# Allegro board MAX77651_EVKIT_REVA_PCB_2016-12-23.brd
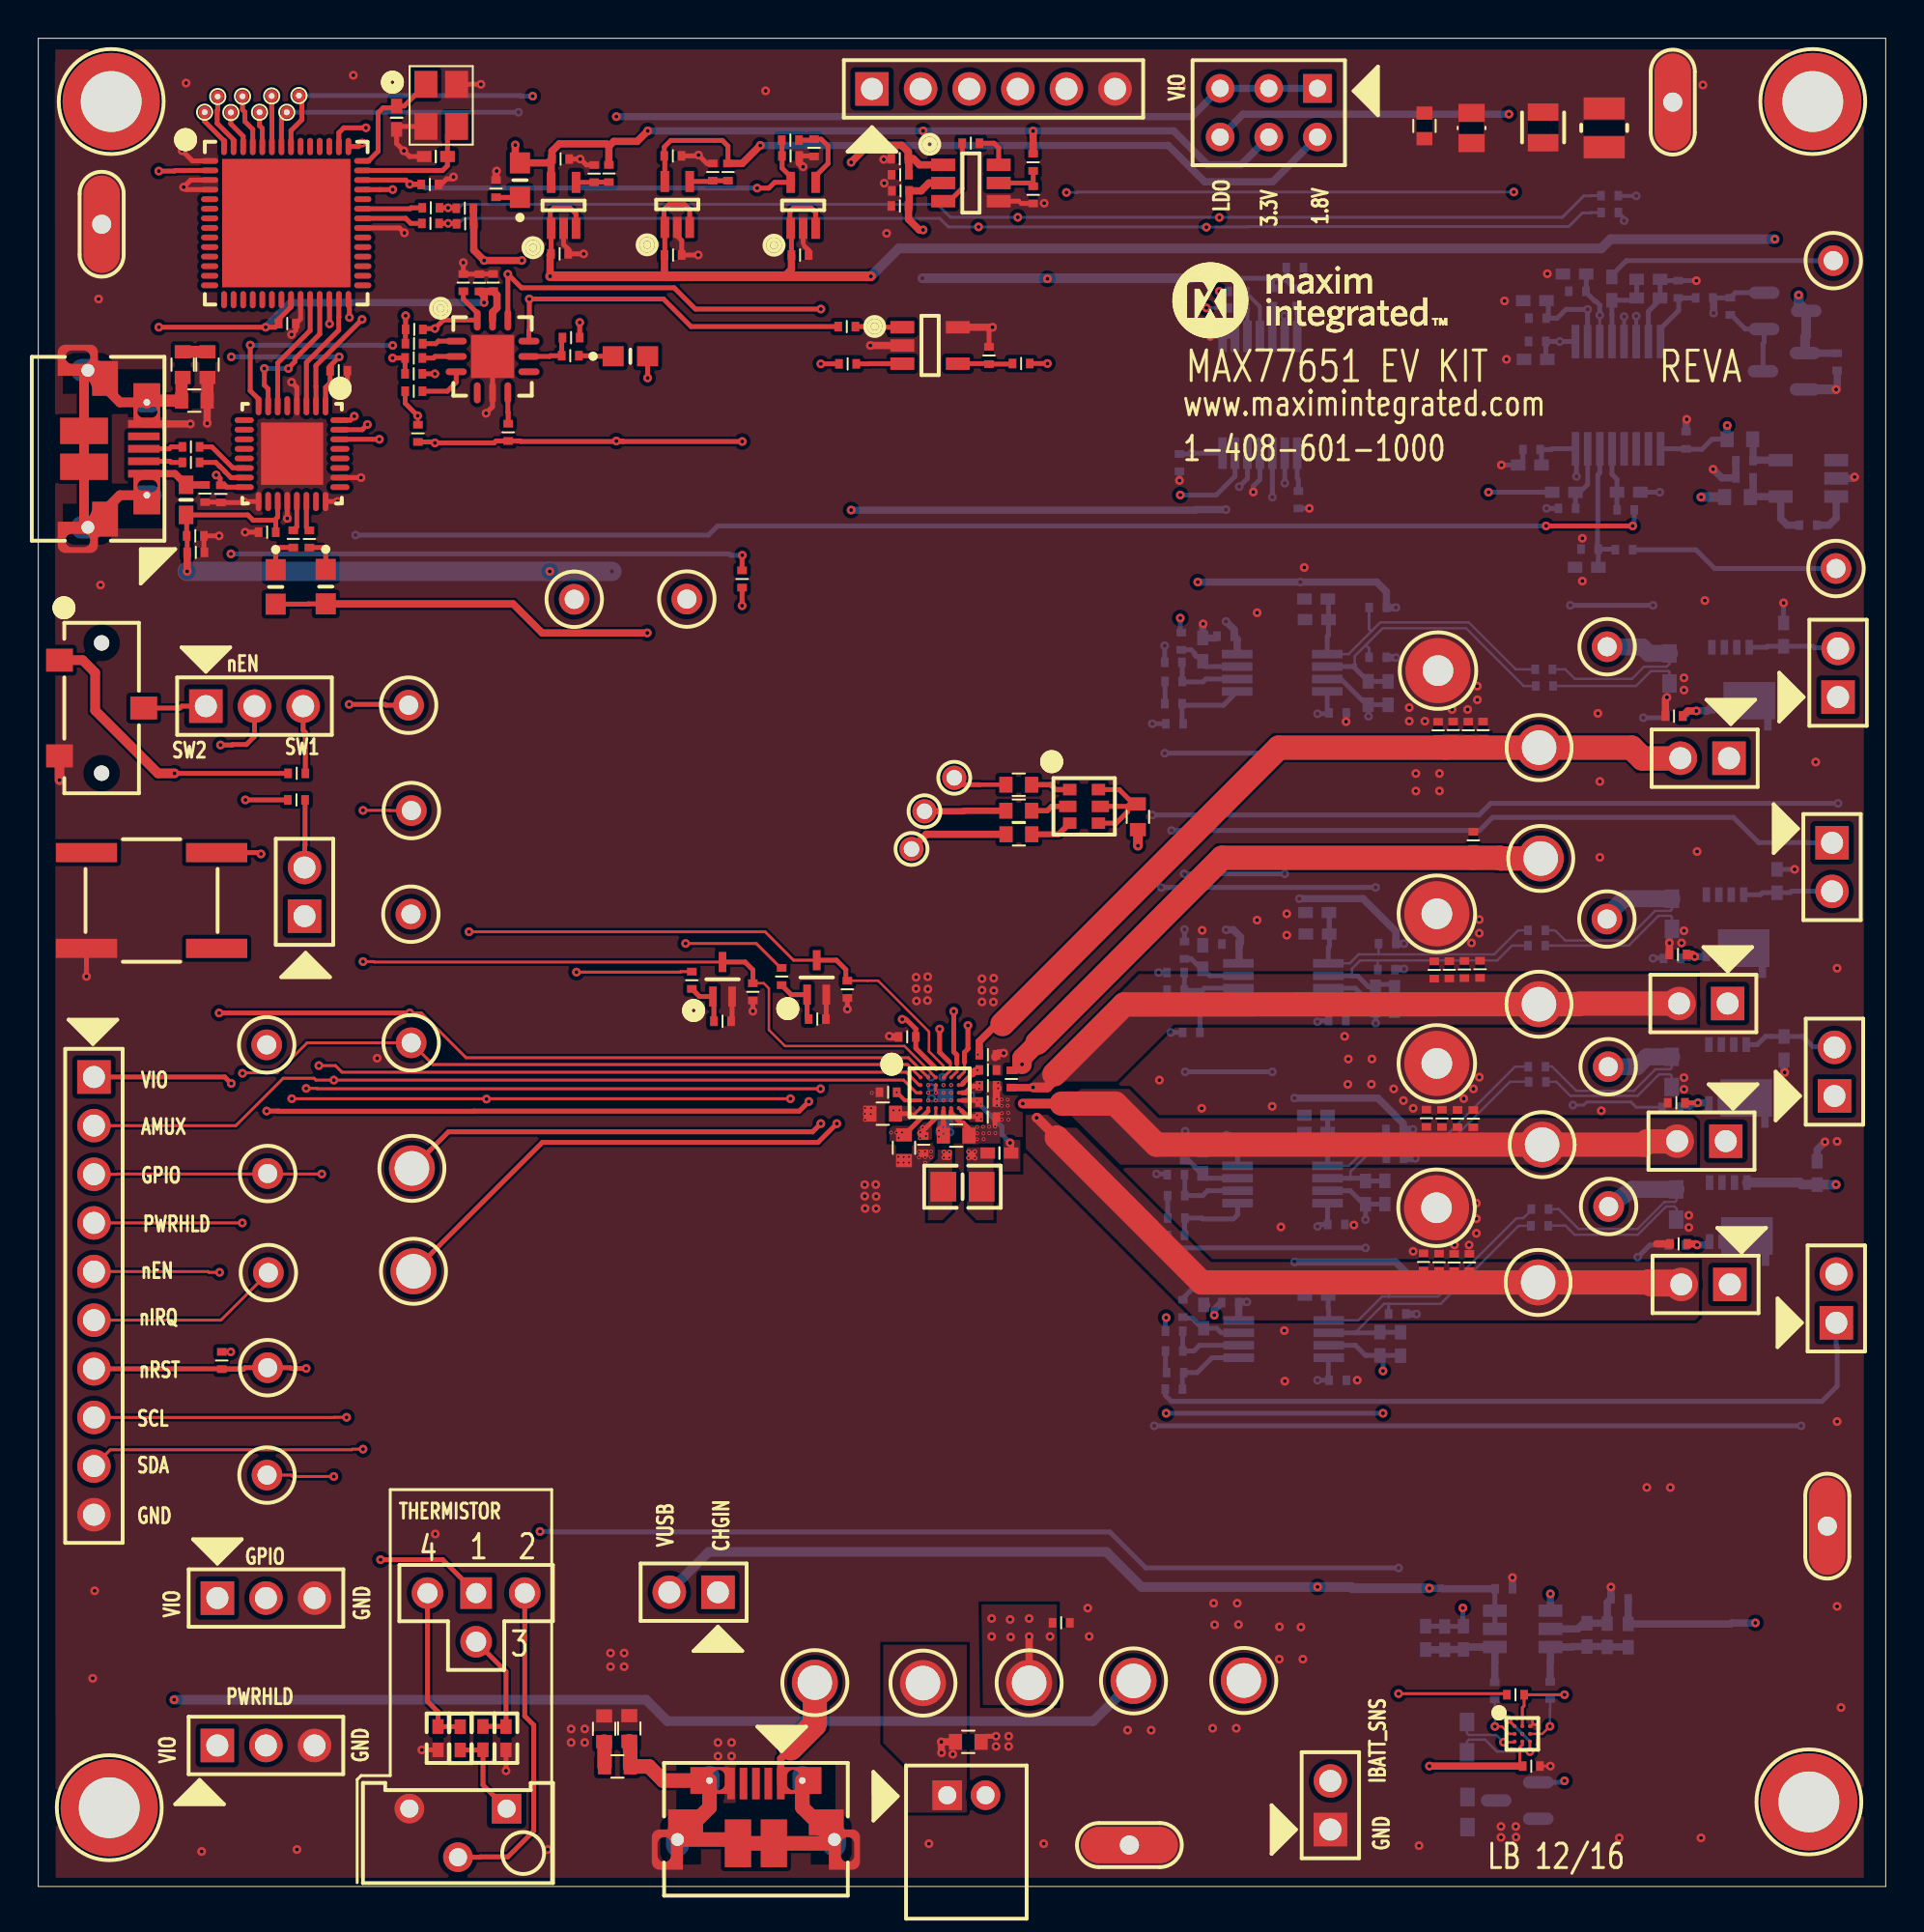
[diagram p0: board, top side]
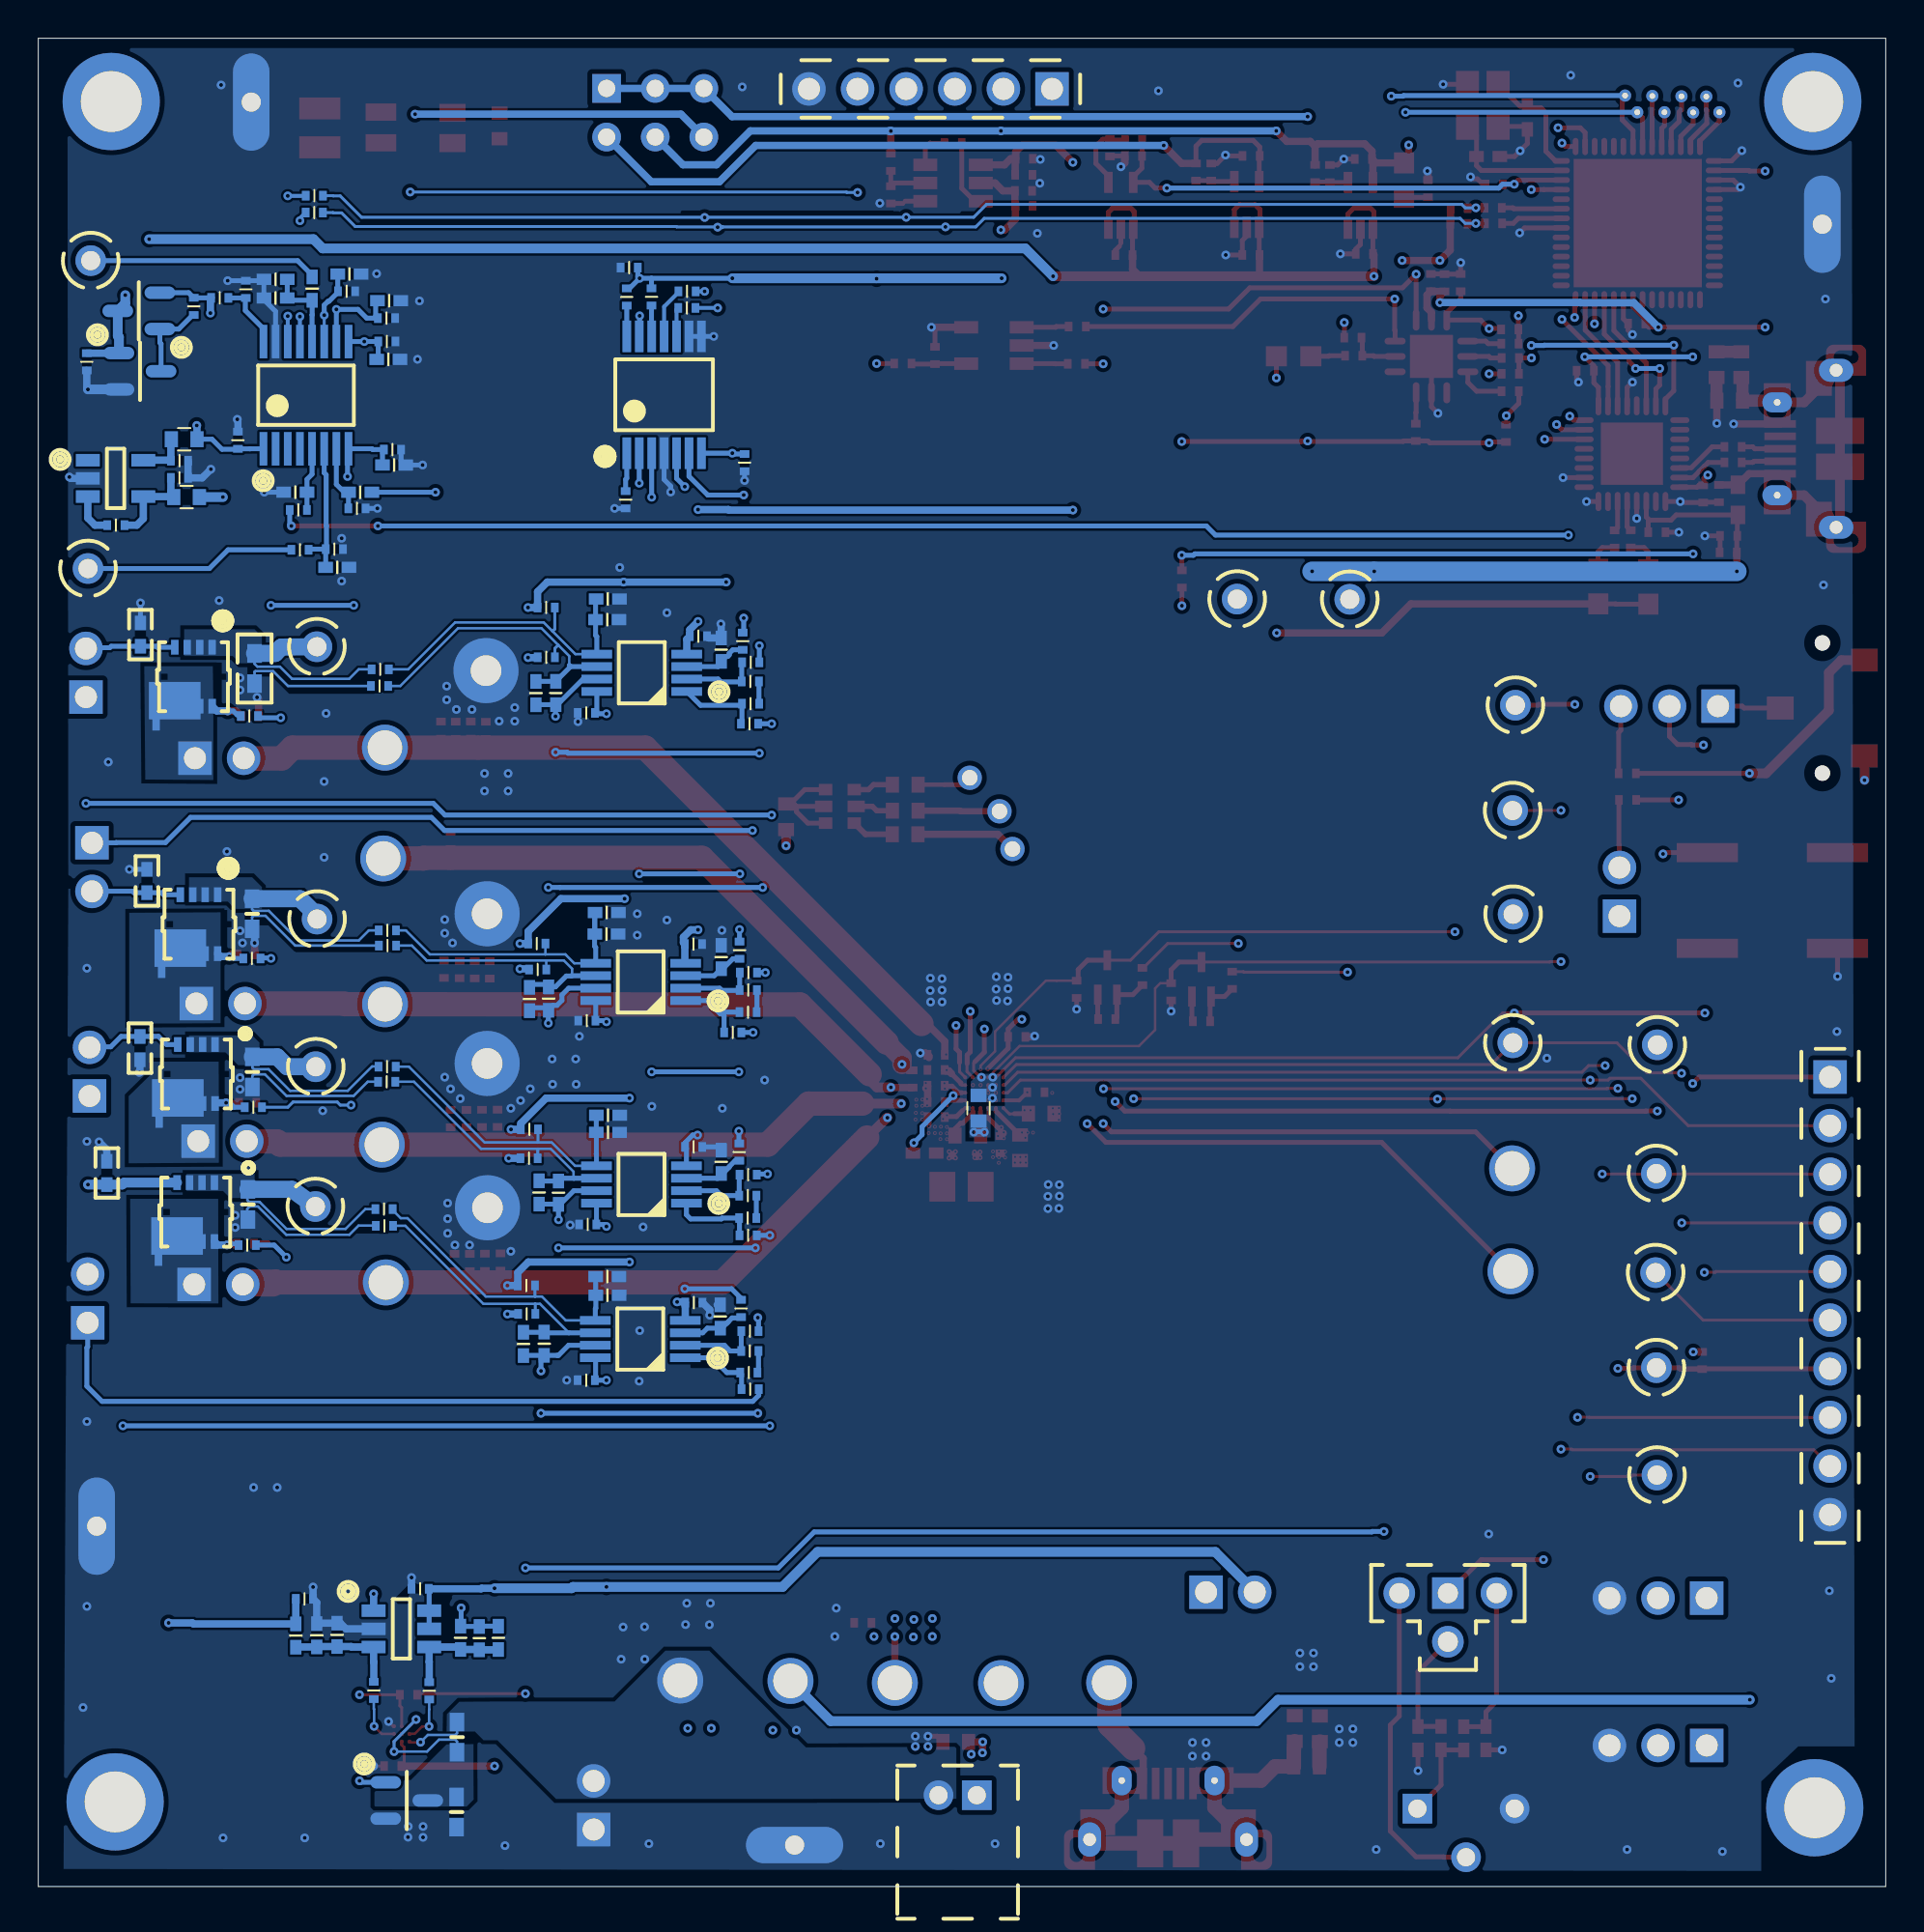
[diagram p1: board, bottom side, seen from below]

Outline 96.52 x 96.52 mm; copper layers: TOP, INTERNAL2, INTERNAL3, BOTTOM. Coordinates in mm from the lower left corner of the outline.
Outline path: 0,96.52 0,0 96.52,0 96.52,96.52 0,96.52

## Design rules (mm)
constraint set DEFAULT: min track width 0.102
net group NIRQ: nets NIRQ UNNAMED_4_EKRESSMD_I87_1
net group NIRQ1: nets NIRQ1 UNNAMED_4_EKRESSMD_I190_2
net group UNNAMED_1_10103592-0001LF_I53_SHIELD10: nets UNNAMED_1_10103592-0001LF_I53_SHIELD10 UNNAMED_1_EKCAPNP_I55_1
net group UNNAMED_4_10103592-0001LF_I2_2: nets UNNAMED_4_10103592-0001LF_I2_2 UNNAMED_4_EKRESSMD_I15_2
net group UNNAMED_4_10103592-0001LF_I2_3: nets UNNAMED_4_10103592-0001LF_I2_3 UNNAMED_4_EKRESSMD_I16_2
net group UNNAMED_4_10103592-0001LF_I2_SHIELD10: nets UNNAMED_4_10103592-0001LF_I2_SHIELD10 UNNAMED_4_EKCAPNP_I29_1
net group UNNAMED_4_EKRESSMD_I17_1: nets UNNAMED_4_EKRESSMD_I17_1 UNNAMED_4_EKRESSMD_I17_2
net group UNNAMED_4_EKRESSMD_I18_1: nets UNNAMED_4_EKRESSMD_I18_1 UNNAMED_4_EKRESSMD_I18_2
net group UNNAMED_4_EKRESSMD_I149_1: nets UNNAMED_4_EKRESSMD_I149_1 UNNAMED_4_EKRESSMD_I151_2
net group UNNAMED_4_EKRESSMD_I150_1: nets UNNAMED_4_EKRESSMD_I150_1 UNNAMED_4_EKRESSMD_I152_2
net group SCL: nets SCL SDA UNNAMED_4_EKRESSMD_I153_1 UNNAMED_4_EKRESSMD_I154_1 UNNAMED_4_EKRESSMD_I171_2 VIO
net group SCL1: nets SCL1 UNNAMED_4_24AA02_I200_SCL UNNAMED_4_EKRESSMD_I109_1
net group SDA1: nets SDA1 UNNAMED_4_24AA02_I200_SDA UNNAMED_4_EKRESSMD_I113_1

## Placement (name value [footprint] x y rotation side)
AIN1  N/A  [TP_180P120D460H]  93.92 68.83 0 top
AIN7  N/A  [TP_180P120D460H]  93.78 84.91 0 top
AMUX  N/A  [TP_180P120D460H]  11.95 21.49 0 top
BATTN  N/A  [TP_C240H180]  62.98 10.76 0 top
C1  22UF  [CAPC1608X90L]  47.96 39.22 180 top
C2  4.7UF  [0603]  44.12 40.36 0 top
C3  1UF  [CAPC1005X50L]  44.4 41.48 0 top
C4  3300PF  [0402]  50.22 38.3 180 top
C5  10UF  [CAPC1005X50L]  49.61 43.44 180 top
C6  10UF  [CAPC1005X50L]  49.61 40.18 180 top
C7  4.7UF  [CAPC1005X50L]  46.26 38.74 90 top
C8  10UF  [CAPC1005X50L]  49.61 40.97 180 top
C9  10UF  [CAPC1005X50L]  49.61 41.82 180 top
C10  0.47UF  [CAPC1608X90L]  29.56 8.24 90 top
C11  22UF  [CAPC1608X90L]  45.23 38.58 270 top
C12  1UF  [CAPC1005X50L]  45.4 44.37 0 top
C13  10UF  [CAPC1005X50L]  49.61 42.64 0 top
C14  0.1UF  [CAPC1005X50L]  49.67 79.96 270 top
C15  22UF  [CAPC1608X90L]  48.59 7.55 0 top
C16  OPEN  [CAPC1005X50L]  53.44 13.77 180 top
C17  10UF  [CAPC1005X50L]  73.13 60.38 270 top
C18  OPEN  [CAPC1005X50L]  74.97 54.64 270 top
C19  OPEN  [CAPC1005X50L]  72.93 47.87 270 top
C20  10UF  [CAPC1005X50L]  72.53 40.12 270 top
C21  OPEN  [CAPC1005X50L]  73.72 47.88 270 top
C22  OPEN  [CAPC1005X50L]  73.34 40.11 270 top
C23  OPEN  [CAPC1005X50L]  73.92 60.39 270 top
C24  OPEN  [CAPC1005X50L]  72.37 32.61 270 top
C25  0.1UF  [CAPC1005X50L]  74.71 60.38 270 top
C26  OPEN  [CAPC1005X50L]  73.19 32.6 270 top
C27  0.1UF  [CAPC1005X50L]  74.51 47.89 270 top
C28  0.1UF  [CAPC1005X50L]  74.15 40.1 270 top
C29  0.1UF  [CAPC1005X50L]  73.97 32.59 270 top
C30  0.01UF  [CAPC1005X50L]  75.33 47.9 270 top
C31  0.01UF  [CAPC1005X50L]  74.97 40.1 270 top
C32  0.01UF  [CAPC1005X50L]  74.77 32.59 270 top
C33  0.01UF  [CAPC1005X50L]  75.48 60.39 270 top
C108  0.1UF  [CAPC1005X50L]  11.96 70.73 0 top
C110  1UF  [CAPC1005X50L]  33.17 85.2 180 top
C111  1UF  [CAPC1005X50L]  33.15 90.38 180 top
C112  1UF  [CAPC1005X50L]  39.8 85.2 180 top
C113  1UF  [CAPC1005X50L]  39.3 90.38 180 top
C114  0.47UF  [CAPC1608X90L]  8.84 79.48 270 top
C115  1UF  [CAPC1005X50L]  23.76 83.76 270 top
C118  1UF  [CAPC1005X50L]  27.24 85.26 180 top
C120  1UF  [CAPC1005X50L]  22.21 83.76 270 top
C129  OPEN  [CAPC1005X50L]  37.33 46.72 90 top
C134  OPEN  [CAPC1005X50L]  42.27 46.86 90 top
C150  0.1UF  [CAPC1005X50L]  13.01 81.62 0 top
C151  0.1UF  [CAPC1005X50L]  20.46 88.89 0 top
C152  15PF  [0402]  18.72 92.37 90 top
C153  15PF  [0402]  20.77 90.35 0 top
C154  4.7UF  [CAPC1005X50L]  8.2 70.54 180 top
C155  0.1UF  [CAPC1005X50L]  8.71 72.75 270 top
C156  0.1UF  [CAPC1005X50L]  9.54 72.73 90 top
C157  0.1UF  [CAPC1005X50L]  23.05 83.75 270 top
C158  1UF  [CAPC1005X50L]  27.29 90.21 180 top
C159  0.1UF  [CAPC1005X50L]  15.7 79.16 0 top
C200  4700PF  [0402]  60.84 48.54 270 bottom
C201  1000PF  [CAPC1005X50L]  59.43 46.82 180 bottom
C202  0.1UF  [CAPC1005X50L]  67.86 45.22 0 bottom
C203  18PF  [0402]  69.86 46.37 90 bottom
C204  18PF  [0402]  66.83 49.74 0 bottom
C205  4700PF  [0402]  77.93 74.24 0 bottom
C206  1000PF  [CAPC1005X50L]  59.45 36.08 180 bottom
C207  0.1UF  [CAPC1005X50L]  67.81 34.57 0 bottom
C208  18PF  [0402]  66.76 39.38 0 bottom
C209  18PF  [0402]  70.35 36.25 90 bottom
C210  4700PF  [0402]  78.23 79.75 0 bottom
C211  1000PF  [CAPC1005X50L]  59.34 27.97 180 bottom
C212  0.1UF  [CAPC1005X50L]  67.89 26.44 0 bottom
C213  18PF  [0402]  70.09 28.35 90 bottom
C214  18PF  [0402]  66.78 30.88 0 bottom
C215  4700PF  [0402]  78.19 82.82 0 bottom
C216  1000PF  [CAPC1005X50L]  59.32 62.93 180 bottom
C217  0.1UF  [CAPC1005X50L]  67.89 61.29 0 bottom
C218  18PF  [0402]  66.79 66.16 0 bottom
C219  18PF  [0402]  69.48 62.33 90 bottom
C220  4700PF  [0402]  80.26 84.21 0 bottom
C221  0.1UF  [CAPC1005X50L]  65.65 84.55 180 bottom
C222  0.1UF  [CAPC1005X50L]  59.62 74.36 90 bottom
C223  0.1UF  [CAPC1005X50L]  65.83 72.42 90 bottom
C224  0.1UF  [CAPC1005X50L]  78 6.29 0 top
C225  330PF  [0402]  74.46 12.99 90 bottom
C226  0.1UF  [CAPC1005X50L]  76.57 15.55 0 bottom
C227  180PF  [0402]  81.97 13.12 90 bottom
C228  1UF  [CAPC1005X50L]  79.87 71.97 0 bottom
C234  0.1UF  [CAPC1005X50L]  89.14 73.56 0 bottom
C235  0.1UF  [CAPC1005X50L]  89.14 74.46 0 bottom
C236  0.1UF  [CAPC1005X50L]  82.61 15.02 0 bottom
C237  0.1UF  [CAPC1005X50L]  85.68 83.41 270 bottom
C238  4700PF  [0402]  84.12 83.93 180 bottom
C239  1UF  [CAPC1005X50L]  85.67 48.67 0 top
C240  1UF  [CAPC1005X50L]  85.58 40.93 0 top
C241  1UF  [CAPC1005X50L]  85.7 33.56 0 top
C242  1UF  [CAPC1005X50L]  85.46 61.12 0 top
C244  0.1UF  [CAPC1005X50L]  86.09 75.53 270 bottom
C248  4700PF  [0402]  60.84 37.85 270 bottom
C249  4700PF  [0402]  83.09 72.82 180 bottom
C250  4700PF  [0402]  60.89 29.77 270 bottom
C251  4700PF  [0402]  60.84 64.59 270 bottom
C252  4700PF  [0402]  80.9 68.89 0 bottom
C268  0.1UF  [CAPC1005X50L]  45.02 87.77 0 top
C269  1UF  [CAPC1005X50L]  45.05 88.55 0 top
C270  1UF  [CAPC1005X50L]  48.72 91.04 0 top
C271  1UF  [CAPC1005X50L]  45.03 89.39 0 top
C272  0.1UF  [CAPC1005X50L]  45.01 90.23 0 top
C273  0.1UF  [CAPC1005X50L]  51.98 88.34 90 top
C274  0.1UF  [CAPC1005X50L]  62.29 49.22 0 bottom
C275  0.1UF  [CAPC1005X50L]  62.28 38.63 0 bottom
C276  0.1UF  [CAPC1005X50L]  62.27 30.5 0 bottom
C277  0.1UF  [CAPC1005X50L]  62.03 65.3 0 bottom
CHGIN  N/A  [TP_C240H180]  40.57 10.65 0 top
D100  LTST-C190YKT  [LEDC1608X80M]  15.02 67.88 270 top
D101  LTST-C190YKT  [LEDC1608X80M]  12.4 67.87 270 top
D102  LTST-C190CKT  [LEDC1608X80M]  25.16 89.11 90 top
D103  LTST-C190CKT  [LEDC1608X80M]  30.93 79.92 0 top
DS1  19-337/R6GHBHC-A01/2T  [LED_R6GHBHC]  54.64 56.41 0 top
FB100  220  [0603#2]  7.72 72.42 270 top
GND1  N/A  [TP_C340H160]  73.13 63.5 90 top
GND2  MAXIMPAD  [EVK_MAXIMPAD]  57.01 2.16 180 top
GND3  MAXIMPAD  [EVK_MAXIMPAD]  3.31 86.81 90 top
GND4  MAXIMPAD  [EVK_MAXIMPAD]  85.39 93.19 270 top
GND5  N/A  [TP_C340H160]  73.05 35.45 0 top
GND6  N/A  [TP_C340H160]  73.07 42.98 0 top
GND7  N/A  [TP_C340H160]  73.07 50.8 0 top
GND8  MAXIMPAD  [EVK_MAXIMPAD]  93.47 18.82 90 top
GPIO  N/A  [TP_180P120D460H]  11.98 37.23 0 top
IN_SBB  N/A  [TP_C240H180]  51.77 10.64 0 top
INLDO  N/A  [TP_C240H180]  78.5 53.69 0 top
J1  10103592-0001LF  [FCI_10103592-0001LF]  37.49 2.45 0 top
J2  PBC10SAAN  [SULLINS_PXC10SAAN]  2.91 42.28 270 top
J3  TSW-103-07-T-S  [SAMTEC_TSW-103-07-T-S]  9.36 15.06 0 top
J4  TSW-103-07-T-S  [SAMTEC_TSW-103-07-T-S]  9.35 7.36 0 top
J5  TSW-103-07-T-S  [SAMTEC_TSW-103-07-T-S]  8.76 61.64 0 top
J6  10103592-0001LF  [FCI_10103592-0001LF]  2.59 75.08 270 top
J7  PEC04SAAN  [JUMPER_3WAY]  22.87 15.32 270 top
J8  TSW-102-07-T-S  [SAMTEC_TSW-102-07-X-S]  13.91 50.68 90 top
J9  S2B-PH-K-S(LF)(SN)  [JST_S2B-PH-K-X]  47.49 4.77 180 top
J10  TSW-102-07-T-S  [SAMTEC_TSW-102-07-X-S]  35.51 15.37 180 top
J100  PBC06SAAN  [SULLINS_PXC06SAAN]  43.56 93.88 0 top
J101  TSW-102-26-T-T  [SAMTEC_TSW-102-26-X-T]  66.83 93.9 270 top
J200  TSW-102-07-T-S  [SAMTEC_TSW-102-07-X-S]  93.72 54.51 270 top
J201  TSW-102-07-T-S  [SAMTEC_TSW-102-07-X-S]  88.26 46.11 180 top
J202  TSW-102-07-T-S  [SAMTEC_TSW-102-07-X-S]  93.84 41.28 90 top
J203  TSW-102-07-T-S  [SAMTEC_TSW-102-07-X-S]  88.16 38.93 180 top
J204  TSW-102-07-T-S  [SAMTEC_TSW-102-07-X-S]  93.94 29.44 90 top
J205  TSW-102-07-T-S  [SAMTEC_TSW-102-07-X-S]  88.38 31.44 180 top
J206  TSW-102-07-T-S  [SAMTEC_TSW-102-07-X-S]  94.03 62.12 90 top
J207  TSW-102-07-T-S  [SAMTEC_TSW-102-07-X-S]  88.33 58.92 180 top
J208  TSW-102-07-T-S  [SAMTEC_TSW-102-07-X-S]  67.51 2.97 90 top
L1  1.5UH  [0805]  48.29 36.55 180 top
L2  0.47UH  [0603]  72.42 91.95 90 top
L3  2.2UH  [0805#2]  74.88 91.84 90 top
L4  2.2UH  [IND_2016]  78.62 91.86 90 top
L5  2.2UH  [IND_2520]  81.81 91.84 90 top
LDO  N/A  [TP_C240H180]  78.41 59.48 0 top
LED0  NA  [TP_C127H81]  47.86 57.9 0 top
LED1  NA  [TP_C127H81]  46.3 56.15 0 top
LED2  NA  [TP_C127H81]  45.62 54.18 0 top
NEN  N/A  [TP_180P120D460H]  19.47 50.78 0 top
NIRQ  N/A  [TP_180P120D460H]  12.02 32.06 0 top
NOREF  -  []  108.1 89.1 0 top
NOREF#2  -  [unnamed#2]  92.71 93.22 0 top
NOREF#3  -  []  0 96.52 0 top
NOREF#4  -  [unnamed#2]  3.81 93.22 0 top
NOREF#5  -  [unnamed#2]  92.51 4.42 0 top
NOREF#6  -  []  12.55 -10.08 0 top
NOREF#7  -  [unnamed#2]  3.71 4.11 0 top
NOREF#8  -  []  -23.98 89.1 0 top
NOREF#9  -  []  61.29 82.75 0 top
NOREF#10  -  []  49.43 150.22 0 top
NOREF#11  -  []  108.1 -9.96 0 top
NOREF#12  -  []  0 0 90 top
NRST  N/A  [TP_180P120D460H]  11.98 27.09 0 top
PO0  N/A  [TP_C25H12]  13.62 93.53 90 top
PO1  N/A  [TP_C25H12]  12.98 92.66 90 top
PO2  N/A  [TP_C25H12]  12.19 93.51 90 top
PO3  N/A  [TP_C25H12]  11.56 92.66 90 top
PO4  N/A  [TP_C25H12]  10.67 93.49 90 top
PO5  N/A  [TP_C25H12]  10.06 92.65 90 top
PO6  N/A  [TP_C25H12]  9.38 93.48 90 top
PO7  N/A  [TP_C25H12]  8.69 92.66 90 top
PWRHLD  N/A  [TP_180P120D460H]  19.48 44.06 0 top
Q100  FDY300NZ  [SOT50P160X90-3M]  35.75 47.38 90 top
Q101  FDY300NZ  [SOT50P160X90-3M]  40.67 47.48 90 top
Q200  IRFHM8337TRPBF  [TRAN_IRF_PQFN8_SINGLE_B]  88.13 50.26 270 bottom
Q201  IRFHM8337TRPBF  [TRAN_IRF_PQFN8_SINGLE_B]  88.26 42.43 270 bottom
Q202  IRFHM8337TRPBF  [TRAN_IRF_PQFN8_SINGLE_B]  88.29 35.22 270 bottom
Q203  IRFHM8337TRPBF  [TRAN_IRF_PQFN8_SINGLE_B]  88.41 63.18 270 bottom
Q204  DMG3420U  [SOT95P237X112-3M]  77.27 4.49 180 bottom
Q205  FDN360P  [SOT95P237X112-3M]  91.27 82.28 0 bottom
Q206  2N7002  [SOT95P237X112-3M]  91.21 79.13 180 bottom
QSCL  N/A  [TP_180P120D460H]  33.88 67.23 0 top
QSDA  N/A  [TP_180P120D460H]  28 67.22 0 top
R1  10K  [0402]  23.23 7.75 90 top
R2  10K  [0402#2]  13.5 58.13 180 top
R3  0  [RESC1608X90L]  30.26 6.27 180 top
R4  1M  [RESC1608X90L]  30.88 8.25 90 top
R5  0  [RESC1608X90L]  47.4 40.65 270 bottom
R6  0  [RESC1608X90L]  51.23 54.95 180 top
R7  0  [RESC1608X90L]  51.22 57.54 180 top
R8  0  [RESC1608X90L]  51.22 56.18 180 top
R9  0  [RESC1608X90L]  57.45 55.86 90 top
R10  10K  [0402#2]  9.59 27.47 90 top
R11  0  [RESC1005X50L]  50.84 42.17 270 top
R12  200K  [BOURNS_3296Y]  21.93 2.8 0 top
R13  10K  [0402]  20.89 7.74 270 top
R14  100K  [RESC1005X50L]  19.84 75.89 270 top
R15  10K  [0402]  22.04 7.74 90 top
R16  150  [0402#2]  13.49 56.75 180 top
R17  0  [RESC1005X50L]  36.77 68.28 90 top
R100  4.7K  [RESC1005X50L]  22.29 87.65 0 top
R103  22  [RESC1005X50L]  7.98 75.18 0 top
R107  2.2K  [RESC1005X50L]  19.61 79 180 top
R108  2.2K  [RESC1005X50L]  19.64 81.32 180 top
R109  100  [RESC1005X50L]  13.32 70.38 270 top
R110  470  [0402#2]  23.92 88.67 90 top
R111  100  [RESC1005X50L]  14.16 70.37 270 top
R115  100K  [RESC1005X50L]  8.23 69.67 0 top
R118  4.7K  [RESC1005X50L]  22.3 86.83 0 top
R122  1M  [RESC1608X90L]  8.15 77.6 0 top
R123  22  [RESC1005X50L]  7.98 74.37 0 top
R135  0  [RESC1005X50L]  19.63 80.57 180 top
R136  0  [RESC1005X50L]  19.62 79.82 180 top
R137  49.9  [RESC1005X50L]  40.7 45.3 0 top
R138  49.9  [RESC1005X50L]  35.75 45.19 0 top
R139  0  [RESC1005X50L]  38.84 47.52 90 top
R141  0  [RESC1005X50L]  34.15 47.33 90 top
R142  0  [RESC1608X90L]  7.54 79.48 90 top
R143  0  [RESC1005X50L]  24.55 75.94 90 top
R148  0  [RESC1005X50L]  20.51 87.67 0 top
R150  22  [RESC1005X50L]  19.62 78.09 180 top
R151  150  [0402#2]  27.8 79.94 180 top
R152  0  [RESC1005X50L]  27.84 80.89 180 top
R155  0  [RESC1005X50L]  20.49 86.85 0 top
R156  105K  [0402#2]  39.29 91.2 0 top
R157  100K  [RESC1005X50L]  40.53 90.8 270 top
R158  169K  [0402#2]  29.81 89.46 270 top
R159  100K  [RESC1005X50L]  29.04 89.45 90 top
R160  47.5K  [0402#2]  36.03 89.53 270 top
R161  100K  [RESC1005X50L]  35.24 89.53 90 top
R162  0  [RESC1005X50L]  42.24 81.47 0 top
R163  0  [RESC1005X50L]  51.35 79.54 0 top
R164  0  [RESC1005X50L]  42.28 79.52 180 top
R201  100  [0402#2]  59.44 45.67 0 bottom
R202  680  [0402#2]  59.42 47.73 180 bottom
R203  20K  [0402#2]  59.88 48.9 270 bottom
R204  0  [RESC1005X50L]  60.24 44.6 180 bottom
R205  4.99K  [0402]  70.85 46.35 90 bottom
R206  4.99K  [0402]  66.82 50.86 0 bottom
R207  1K  [RESC1005X50L]  78.28 49.93 0 bottom
R208  1K  [RESC1005X50L]  78.28 49.14 0 bottom
R210  1M  [0402]  90.84 52.51 270 bottom
R211  1  [0603#2]  85.35 50.8 270 bottom
R212  0  [RESC1005X50L]  85.36 48.47 180 bottom
R213  OPEN  [RESC1005X50L]  78.01 75.04 180 bottom
R214  100K  [RESC1005X50L]  65.78 83.01 90 bottom
R222  100  [0402#2]  59.46 34.91 0 bottom
R223  680  [0402#2]  59.43 37.17 180 bottom
R224  20K  [0402#2]  59.89 38.36 270 bottom
R225  0  [RESC1005X50L]  59.44 34.01 180 bottom
R226  4.99K  [0402]  66.75 40.28 0 bottom
R227  510K  [0402#2]  85.28 40.7 180 bottom
R228  4.99K  [0402]  69.34 36.23 90 bottom
R229  1K  [RESC1005X50L]  78.3 42.82 0 bottom
R230  1K  [RESC1005X50L]  78.32 42.03 0 bottom
R231  1M  [0402]  91.21 43.78 90 bottom
R233  1  [0603#2]  85.34 42.54 270 bottom
R234  510K  [0402#2]  78.31 80.69 180 bottom
R235  100  [0402#2]  59.4 26.84 0 bottom
R236  680  [0402#2]  59.34 29 180 bottom
R237  20K  [0402#2]  59.8 30.19 270 bottom
R238  0  [RESC1005X50L]  59.33 25.97 180 bottom
R239  4.99K  [0402]  71.17 28.33 90 bottom
R240  4.99K  [0402]  66.79 31.86 0 bottom
R242  1K  [RESC1005X50L]  78.46 35.38 0 bottom
R243  1K  [RESC1005X50L]  78.44 34.5 0 bottom
R244  1M  [0402]  92.94 37.27 270 bottom
R245  1  [0603#2]  85.57 35.62 270 bottom
R246  510K  [0402#2]  85.61 33.5 180 bottom
R247  510K  [0402#2]  78.33 81.91 180 bottom
R248  100  [0402#2]  59.31 61.77 0 bottom
R249  680  [0402#2]  59.3 63.93 180 bottom
R250  20K  [0402#2]  59.72 65.03 270 bottom
R251  0  [RESC1005X50L]  59.36 60.72 180 bottom
R252  4.99K  [0402]  66.76 67.24 0 bottom
R253  4.99K  [0402]  70.52 62.32 90 bottom
R254  1K  [RESC1005X50L]  78.66 63.57 0 bottom
R255  1K  [RESC1005X50L]  78.69 62.7 0 bottom
R257  1M  [0402]  91.18 65.38 270 bottom
R258  1  [0603#2]  85.22 63.61 270 bottom
R259  0  [RESC1005X50L]  85.49 61.13 180 bottom
R260  OPEN  [RESC1005X50L]  80.41 83.31 180 bottom
R261  0.1  [0603#2]  74.64 7.8 270 bottom
R262  10  [0603#2]  74.67 3.89 270 bottom
R263  1K  [RESC1005X50L]  76.09 10.22 90 bottom
R264  1K  [RESC1005X50L]  78.99 10.24 90 bottom
R265  64.9K  [0402]  83.06 13.1 270 bottom
R266  64.9K  [0402]  73.48 12.97 90 bottom
R267  64.9K  [0402]  72.48 12.99 90 bottom
R268  64.9K  [0402]  80.91 13.14 90 bottom
R269  1K  [0402]  79.7 72.81 0 bottom
R277  0  [RESC1608X90L]  88.77 72.56 0 bottom
R279  0  [RESC1608X90L]  88.9 75.58 180 bottom
R280  100K  [RESC1005X50L]  92.47 71.09 0 bottom
R281  10K  [0402]  82.21 83.45 270 bottom
R282  10K  [0402]  84.12 82.96 0 bottom
R283  100K  [RESC1005X50L]  64.48 83.01 270 bottom
R284  100K  [0402#2]  77.18 10.02 0 top
R285  0  [RESC1005X50L]  82.93 71.89 180 bottom
R286  0  [RESC1005X50L]  87.04 82.96 180 bottom
R287  10K  [0402#2]  93.99 79.62 270 bottom
R288  10K  [0402#2]  88.4 82.52 270 bottom
R289  100  [0402#2]  51.98 90.05 270 top
R293  470K  [0402#2]  70.47 49.24 0 bottom
R294  649K  [0402#2]  70.43 47.89 180 bottom
R295  470K  [0402#2]  70.86 39.54 0 bottom
R296  649K  [0402#2]  70.88 38.03 180 bottom
R297  470K  [0402#2]  71.02 31.39 0 bottom
R298  649K  [0402#2]  71 29.9 180 bottom
R299  470K  [0402#2]  69.98 66.79 0 bottom
R300  649K  [0402#2]  69.98 64.19 180 bottom
R301  1M  [0402#2]  81.05 69.84 180 bottom
R302  0  [RESC1005X50L]  82.85 69.81 180 bottom
R303  0  [RESC1005X50L]  82.1 88.3 0 bottom
R304  0  [RESC1005X50L]  82.1 87.42 0 bottom
R305  0  [RESC1005X50L]  62.63 82.44 0 bottom
R306  0  [RESC1005X50L]  62.62 83.3 0 bottom
RT1  10K  [0402]  24.44 7.74 270 top
SBB0  N/A  [TP_C240H180]  78.4 46.08 0 top
SBB1  N/A  [TP_C240H180]  78.57 38.74 0 top
SBB2  N/A  [TP_C240H180]  78.36 31.55 0 top
SCL  N/A  [TP_180P120D460H]  19.35 61.69 0 top
SDA  N/A  [TP_180P120D460H]  19.49 56.19 0 top
SW1  EVQ-Q2K03W  [SW_EVQ-Q2X03W]  5.92 51.49 180 top
SW2  CL-SB-12B-11  [SW_CL-SB-12B-1X]  3.31 61.54 0 top
TBIAS  N/A  [TP_C240H180]  19.6 32.13 0 top
THM  N/A  [TP_C240H180]  19.52 37.5 0 top
U1  MAX77651  [BGA30C40P6X5_275X215X69M]  47.09 41.45 0 top
U100  MAXQ2000-RBX+  [QFN50P800X800X80-57M]  12.95 86.87 0 top
U101  FT232RQ  [QFN50P500X500X100-33V2M]  13.26 74.83 270 top
U102  MAX8512EXK  [SOT65P210X110-5M]  27.44 87.79 90 top
U103  MAX8512EXK  [SOT65P210X110-5M]  33.38 87.84 90 top
U104  MAX8512EXK  [SOT65P210X110-5M]  39.96 87.8 90 top
U107  MAX3395EETC  [QFN80P400X400X80-13M]  23.73 79.91 0 top
U108  24AA02T-I/OT  [SOT95P280X145-5M]  46.59 80.48 0 top
U200  MAX44251AUA+  [SOP65P490X110-8M]  65.05 47.24 0 bottom
U201  MAX44251AUA+  [SOP65P490X110-8M]  65.01 36.66 0 bottom
U202  MAX44251AUA+  [SOP65P490X110-8M]  65.07 28.59 0 bottom
U203  MAX44251AUA+  [SOP65P490X110-8M]  64.99 63.38 0 bottom
U205  MAX5815AAUD+  [SOP65P640X120-14M]  63.82 77.9 90 bottom
U206  MAX14689EWL+  [BGA9C40P3X3_126X126X69M]  77.53 7.97 0 top
U207  MAX4238AUT+  [SOT95P280X145-6M]  77.55 13.46 180 bottom
U209  MAX11614EEE+  [SOP63P600X175-16M]  82.53 77.88 90 bottom
U210  MAX6037BAUK41+  [SOT95P280X145-5M]  92.48 73.54 180 bottom
U211  MAX1697UEUT+  [SOT95P280X145-6M]  48.73 88.96 0 top
VBATT  N/A  [TP_C240H180]  46.22 10.62 0 top
VIL_LDO  N/A  [TP_180P120D460H]  81.97 64.74 0 top
VIL_SBB0  N/A  [TP_180P120D460H]  81.95 50.52 0 top
VIL_SBB1  N/A  [TP_180P120D460H]  82.02 42.81 0 top
VIL_SBB2  N/A  [TP_180P120D460H]  82.04 35.51 0 top
VL  N/A  [TP_180P120D460H]  11.93 43.95 0 top
VSYS  N/A  [TP_C240H180]  57.22 10.74 0 top
Y101  16MHZ  [XTAL320X250X070M]  21.05 93.02 270 top

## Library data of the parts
AIN1 AIN7 VIL_LDO VIL_SBB0-VIL_SBB2 VL = TP: part number: TP_TP-TP_180P120D460H,N/A,02-TPMINI5000-00
AMUX GPIO NEN NIRQ NRST PWRHLD QSCL QSDA SCL SDA = TP: part number: TP_TP-TP_180P120D460H,N/A,02-TPMINI5002-00
BATTN CHGIN IN_SBB INLDO LDO SBB0-SBB2 TBIAS THM VBATT VSYS = TP: alternate symbols: TP_C340H160L; part number: TP_TP-TP_C240H180,N/A,02-TPMINI5010-00
C1 C11 C15 = EK_CAP_NP: part number: EK_CAP_NP_0603_FF-CAPC1608X90L,22UF,20-0022U-A48
C2 = CAP_NP: alternate symbols: 0603_NOSILK,CAPC1608X90L; part number: CAP_NP_0603CAP-0603,4.7UF,20-004U7-L3
C3 C12 C110-C113 C115 C118 C120 C158 C239-C242 = EK_CAP_NP: part number: EK_CAP_NP_0402_FF-CAPC1005X50L,1UF,20-0001U-B65
C4 = CAP_NP: alternate symbols: (0402_NOSILK); part number: CAP_NP_0402CAP-0402,3300PF,20-3300P-A0Z
C5 C6 C8 C9 C13 C17 C20 = EK_CAP_NP: part number: EK_CAP_NP_0402_FF-CAPC1005X50L,10UF,20-0010U-B65
C7 = EK_CAP_NP: part number: EK_CAP_NP_0402_FF-CAPC1005X50L,4.7UF,20-004U7-33A
C10 C114 = EK_CAP_NP: part number: EK_CAP_NP_0603_FF-CAPC1608X90L,0.47UF,20-00U47-16; signal model: DEFAULT_CAPACITOR_470000pF_2_1
C14 C156 C157 = EK_CAP_NP: part number: EK_CAP_NP_0402_FF-CAPC1005X50L,0.1UF,20-000U1-12; signal model: DEFAULT_CAPACITOR_100000pF_2_1
C16 C18 C19 C21-C24 C26 = EK_CAP_NP: alternate symbols: 0402,0402_NOSILK; part number: EK_CAP_NP_0402_FF-CAPC1005X50L,OPEN,N/A
C25 C27-C29 = EK_CAP_NP: part number: EK_CAP_NP_0402_FF-CAPC1005X50L,0.1UF,20-000U1-33
C30-C33 = EK_CAP_NP: part number: EK_CAP_NP_0402_FF-CAPC1005X50L,0.01UF,20-00U01-B8
C108 C150 C151 C155 C159 C202 C207 C212 C217 C221-C224 C226 C234-C237 C244 C268 C272-C277 = EK_CAP_NP: part number: EK_CAP_NP_0402_FF-CAPC1005X50L,0.1UF,20-000U1-12
C129 C134 = EK_CAP_NP: alternate symbols: 0402,0402_NOSILK; part number: EK_CAP_NP_0402_FF-CAPC1005X50L,OPEN,N/A; signal model: DEFAULT_CAPACITOR_0.001pF_2_1
C152 C153 = CAP_NP: alternate symbols: 0402_NOSILK,CAPC1005X50L; part number: CAP_NP_0402CAP-0402,15PF,20-0015P-F3
C154 = EK_CAP_NP: part number: EK_CAP_NP_0402_FF-CAPC1005X50L,4.7UF,20-004U7-33A; signal model: DEFAULT_CAPACITOR_4.7e+06pF_2_1
C200 C205 C210 C215 C220 C238 C248-C252 = CAP_NP: alternate symbols: (0402_NOSILK); part number: CAP_NP_0402CAP-0402,4700PF,20-4700P-A0Z
C201 C206 C211 C216 = EK_CAP_NP: part number: EK_CAP_NP_0402_FF-CAPC1005X50L,1000PF,20-1000P-E7
C203 C204 C208 C209 C213 C214 C218 C219 = CAP_NP: alternate symbols: 0402_NOSILK,CAPC1005X50L; part number: CAP_NP_0402CAP-0402,18PF,20-0018P-27
C225 = CAP_NP: alternate symbols: (0402_NOSILK); part number: CAP_NP_0402CAP-0402,330PF,20-0330P-27J
C227 = CAP_NP: alternate symbols: (0402_NOSILK); part number: CAP_NP_0402CAP-0402,180PF,20-0180P-27J
C228 = EK_CAP_NP: part number: EK_CAP_NP_0402_FF-CAPC1005X50L,1UF,20-0001U-33
C269-C271 = EK_CAP_NP: part number: EK_CAP_NP_0402_FF-CAPC1005X50L,1UF,20-0001U-E2
D100 D101 = LED: part number: LED_LEDC1608X80M-LEDC1608X80M,LTST-C190YKT,30-LTSTC190YKT-00
D102 D103 = LED: part number: LED_LEDC1608X80M-LEDC1608X80M,LTST-C190CKT,30-LTSTC190CKT-00
DS1 = LED_6P: part number: LED_6P_R6GHBHC-LED_R6GHBHC,19-337/R6GHBHC-A01/2T,30-19337R6GHBHCA012T-00
FB100 = INDUCT: alternate symbols: (0603_NOSILK); part number: INDUCT_0603-0603,220,50-00220-SM12A; signal model: DEFAULT_INDUCTOR_220.000000nH_1_2
GND1 GND5-GND7 = TP: alternate symbols: TP_C340H160L; part number: TP_TP-TP_C340H160,N/A,02-TPMINI5011-00
GND2-GND4 GND8 = EVK_MAXIMPAD: alternate symbols: EVK_MAXIMPAD_ALT; part number: EVK_MAXIMPAD_MISC-EVK_MAXIMPAD,MAXIMPAD,01-9020BUSS20AWG-00
J1 J6 = 10103592-0001LF: part number: 10103592-0001LF_SMT-FCI_10103592-0001LF,10103592-0001LF,01-101035920001LF5P-26
J2 = HEADER_10P: part number: HEADER_10P_TH-SULLINS_PXC10SAAN,PBC10SAAN,01-PBC10SAAN10P-21
J3-J5 = HEADER_3P: part number: HEADER_3P_SIP-SAMTEC_TSW-103-07-T-S,TSW-103-07-T-S,01-TSW10307TS3P-17
J7 = EVK_JUMPER: part number: EVK_JUMPER_3WAY-JUMPER_3WAY,PEC04SAAN,01-PEC04SAAN4P-21
J8 J10 J200-J208 = HEADER_2P: part number: HEADER_2P_TH-SAMTEC_TSW-102-07-X-S,TSW-102-07-T-S,01-TSW10207TS2P-17
J9 = HEADER_2P: part number: HEADER_2P_RA-JST_S2B-PH-K-X,S2B-PH-K-S(LF)(SN),01-S2BPHKS2P-19
J100 = HEADER_6P: part number: HEADER_6P_TH-SULLINS_PXC06SAAN,PBC06SAAN,01-PBC06SAAN6P-21
J101 = HEADER_2P_X_3R: part number: HEADER_2P_X_3R_TH-SAMTEC_TSW-102-26-X-T,TSW-102-26-T-T,01-TSW10226TT6P-17
L1 = EVKIT_INDUCT: alternate symbols: INDC2012X145L; part number: EVKIT_INDUCT_IND_0805-0805,1.5UH,50-001U5-0LP
L2 = INDUCT: alternate symbols: 0603_NOSILK,INDC1608X90L; part number: INDUCT_0603-0603,0.47UH,50-00U47-0DK
L3 = EVKIT_INDUCT: alternate symbols: INDC2012X145L; part number: EVKIT_INDUCT_IND_0805-0805,2.2UH,50-002U2-0LM
L4 = EVKIT_INDUCT: alternate symbols: INDC2016X100L; part number: EVKIT_INDUCT_IND_0806-IND_2016,2.2UH,50-002U2-0LO
L5 = EVKIT_INDUCT: alternate symbols: INDC2520X120L; part number: EVKIT_INDUCT_2520-IND_2520,2.2UH,50-002U2-0LN
LED0-LED2 = TP: part number: TP_TP-TP_C127H81,NA,NA
PO0-PO7 = TP: part number: TP_TP-TP_C25H12,N/A,N/A
Q100 Q101 = TRAN_NCH_3P: part number: TRAN_NCH_3P_SC89_TRENCH-SOT50P160X90-3M,FDY300NZ,90-FDY300NZ-28
Q200-Q203 = TRAN_NCH_8P: part number: TRAN_NCH_8P_PQFN8-TRAN_IRF_PQFN8_SINGLE_B,IRFHM8337TRPBF,90-IRFHM8337-10
Q204 = TRAN_NCH_3P: part number: TRAN_NCH_3P_SOT23-SOT95P237X112-3M,DMG3420U,90-DMG3420U-16
Q205 = TRAN_PCH_3P: part number: TRAN_PCH_3P_SOT-23-SOT95P237X112-3M,FDN360P,90-FDC360P-25
Q206 = TRAN_NCH_3P: part number: TRAN_NCH_3P_SOT23-SOT95P237X112-3M,2N7002,90-2N7002-06
R1 R2 R10 R13 R15 R281 R282 R287 R288 = RES: alternate symbols: 0402_NOSILK,RESC1005X50L,RES0402-NOT_FOR_TEST; part number: RES_0402RES-0402,10K,80-0010K-23
R3 R142 = EK_RES_SMD: part number: EK_RES_SMD_0603_FF-RESC1608X90L,0,80-0000R-27; signal model: DEFAULT_RESISTOR_0.001OHM_2_1
R4 R122 = EK_RES_SMD: part number: EK_RES_SMD_0603_FF-RESC1608X90L,1M,80-0001M-19; signal model: DEFAULT_RESISTOR_0.001OHM_2_1
R5-R9 R277 R279 = EK_RES_SMD: part number: EK_RES_SMD_0603_FF-RESC1608X90L,0,80-0000R-27
R11 R17 R204 R212 R225 R238 R251 R259 R285 R286 R302-R306 = EK_RES_SMD: part number: EK_RES_SMD_0402_FF-RESC1005X50L,0,80-0000R-26
R12 = RES_POT: part number: RES_POT_POT-BOURNS_3296Y,200K,80-0200K-F0A
R14 R157 R159 R161 R214 R280 R283 = EK_RES_SMD: part number: EK_RES_SMD_0402_FF-RESC1005X50L,100K,80-0100K-23
R16 R151 = RES: alternate symbols: (0402_NOSILK,RESC1005X50L); part number: RES_0402RES-0402,150,80-0150R-23
R100 R118 = EK_RES_SMD: part number: EK_RES_SMD_0402_FF-RESC1005X50L,4.7K,80-004K7-23; signal model: DEFAULT_RESISTOR_4700OHM_2_1
R103 R123 = EK_RES_SMD: part number: EK_RES_SMD_0402_FF-RESC1005X50L,22,80-0022R-23; signal model: DEFAULT_RESISTOR_22.000000OHM_1_2
R107 R108 = EK_RES_SMD: part number: EK_RES_SMD_0402_FF-RESC1005X50L,2.2K,80-002K2-23; signal model: DEFAULT_RESISTOR_470.000000OHM_1_2
R109 R111 = EK_RES_SMD: part number: EK_RES_SMD_0402_FF-RESC1005X50L,100,80-0100R-23; signal model: DEFAULT_RESISTOR_100.000000OHM_2_1
R110 = RES: alternate symbols: (0402_NOSILK,RESC1005X50L); part number: RES_0402RES-0402,470,80-0470R-23
R115 = EK_RES_SMD: part number: EK_RES_SMD_0402_FF-RESC1005X50L,100K,80-0100K-23; signal model: DEFAULT_RESISTOR_100000OHM_1_2
R135 R136 R148 R152 R155 R162-R164 = EK_RES_SMD: part number: EK_RES_SMD_0402_FF-RESC1005X50L,0,80-0000R-26; signal model: DEFAULT_RESISTOR_22.000000OHM_2_1
R137 R138 = EK_RES_SMD: part number: EK_RES_SMD_0402_FF-RESC1005X50L,49.9,80-049R9-23; signal model: DEFAULT_RESISTOR_49.900000OHM_1_2
R139 R141 R143 = EK_RES_SMD: part number: EK_RES_SMD_0402_FF-RESC1005X50L,0,80-0000R-26; signal model: DEFAULT_RESISTOR_0.001OHM_1_2
R150 = EK_RES_SMD: part number: EK_RES_SMD_0402_FF-RESC1005X50L,22,80-0022R-23; signal model: DEFAULT_RESISTOR_22.000000OHM_2_1
R156 = RES: alternate symbols: (0402_NOSILK,RESC1005X50L); part number: RES_0402RES-0402,105K,80-0105K-18
R158 = RES: alternate symbols: (0402_NOSILK,RESC1005X50L); part number: RES_0402RES-0402,169K,80-0169K-23
R160 = RES: alternate symbols: (0402_NOSILK,RESC1005X50L); part number: RES_0402RES-0402,47.5K,80-047K5-23
R201 R222 R235 R248 R289 = RES: alternate symbols: 0402_NOSILK,RESC1005X50L,RES0402-NOT_FOR_TEST; part number: RES_0402RES-0402,100,80-0100R-23
R202 R223 R236 R249 = RES: alternate symbols: (0402_NOSILK,RESC1005X50L); part number: RES_0402RES-0402,680,80-0680R-23
R203 R224 R237 R250 = RES: alternate symbols: (0402_NOSILK,RESC1005X50L); part number: RES_0402RES-0402,20K,80-0020K-23
R205 R206 R226 R228 R239 R240 R252 R253 = RES: alternate symbols: (0402_NOSILK,RESC1005X50L); part number: RES_0402RES-0402,4.99K,80-04K99-23
R207 R208 R229 R230 R242 R243 R254 R255 R263 R264 = EK_RES_SMD: part number: EK_RES_SMD_0402_FF-RESC1005X50L,1K,80-0001K-23
R210 R231 R244 R257 R301 = RES: alternate symbols: (0402_NOSILK,RESC1005X50L); part number: RES_0402RES-0402,1M,80-0001M-23
R211 R233 R245 R258 = RES: alternate symbols: (0603_NOSILK); part number: RES_0603RES-0603,1,80-0001R-24
R213 R260 = EK_RES_SMD: alternate symbols: 0402,0402_NOSILK,; part number: EK_RES_SMD_0402_FF-RESC1005X50L,OPEN,N/A
R227 R234 R246 R247 = RES: alternate symbols: (0402_NOSILK,RESC1005X50L); part number: RES_0402RES-0402,510K,80-0510K-49
R261 = RES: alternate symbols: (0603_NOSILK); part number: RES_0603RES-0603,0.1,80-000R1-AA14
R262 = RES: alternate symbols: (0603_NOSILK); part number: RES_0603RES-0603,10,80-0010R-24
R265-R268 = RES: alternate symbols: (0402_NOSILK,RESC1005X50L); part number: RES_0402RES-0402,64.9K,80-064K9-23
R269 = RES: alternate symbols: 0402_NOSILK,RESC1005X50L,RES0402-NOT_FOR_TEST; part number: RES_0402RES-0402,1K,80-0001K-23
R284 = RES: alternate symbols: 0402_NOSILK,RESC1005X50L; part number: RES_0402RES-0402,100K,80-0100K-23
R293 R295 R297 R299 = RES: alternate symbols: (0402_NOSILK,RESC1005X50L); part number: RES_0402RES-0402,470K,80-0470K-23
R294 R296 R298 R300 = RES: alternate symbols: 0402_NOSILK,RESC1005X50L; part number: RES_0402RES-0402,649K,80-0649K-AA18
RT1 = THERMISTOR_SMD: part number: THERMISTOR_SMD_0402-0402,10K,83-0010K-23A
SW1 = EVQ-Q2XXXX: part number: EVQ-Q2XXXX_SMT-SW_EVQ-Q2X03W,EVQ-Q2K03W,11-EVQQ2K03W-00
SW2 = CL-SB-12B-1X: part number: CL-SB-12B-1X_SMD-SW_CL-SB-12B-1X,CL-SB-12B-11,11-CLSB12B11-00
U1 = EK_MAX77651: alternate symbols: BGA30C40P6X5_275X215X69L; part number: EK_MAX77651_WLP30-BGA30C40P6X5_275X215X69M,MAX77651,N/A
U100 = MAXQ2000: part number: MAXQ2000_TQFN56-EP-QFN50P800X800X80-57M,MAXQ2000-RBX+,10-MAXQ2000RBX-T
U101 = FT232RQ: part number: FT232RQ_QFN32-EP-QFN50P500X500X100-33V2M,FT232RQ,10-FT232RQ-G
U102-U104 = MAX8512: part number: MAX8512_SC70-SOT65P210X110-5M,MAX8512EXK,10-MAX8512EXK-X
U107 = MAX3395E: part number: MAX3395E_TQFN-QFN80P400X400X80-13M,MAX3395EETC,10-MAX3395EETC-T
U108 = 24AA02: part number: 24AA02_SOT23-5-SOT95P280X145-5M,24AA02T-I/OT,10-24AA02TIOT-U
U200-U203 = MAX44251: part number: MAX44251_SPLIT_UMAX8-SOP65P490X110-8M,MAX44251AUA+,10-MAX44251AUA-U
U205 = MAX5815: part number: MAX5815_TSSOP14-SOP65P640X120-14M,MAX5815AAUD+,10-MAX5815AAUD-U
U206 = MAX14689: alternate symbols: BGA9C40P3X3_126X126X69L; part number: MAX14689_WLP9-BGA9C40P3X3_126X126X69M,MAX14689EWL+,10-MAX14689EWL-W
U207 = MAX4238: part number: MAX4238_SOT23-6-SOT95P280X145-6M,MAX4238AUT+,10-MAX4238AUT-U
U209 = MAX11614: part number: MAX11614_QSOP16-SOP63P600X175-16M,MAX11614EEE+,10-MAX11614EEE-U
U210 = MAX6037: part number: MAX6037_SOT23-5-SOT95P280X145-5M,MAX6037BAUK41+,10-MAX6037BAUK41-U
U211 = MAX1697: part number: MAX1697_SOT23-6-SOT95P280X145-6M,MAX1697UEUT+,10-MAX1697UEUT-U
Y101 = XTAL: part number: XTAL_XTAL320X250X070M-XTAL320X250X070M,16MHZ,60-0016M-26A

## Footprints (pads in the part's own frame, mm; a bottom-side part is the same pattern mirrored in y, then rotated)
0402
  rect 0.762x0.584 smd: 1(-0.61,0) 2(0.61,0)
0402#2
  rect 0.4x0.5 smd: 1(-0.45,0) 2(0.45,0)
0603
  rect 0.69x0.83 smd: 1(-0.67,0) 2(0.67,0)
0603#2
  rect 0.965x0.762 smd: 1(-0.787,0) 2(0.787,0)
0805
  rect 1.35x1.55 smd: 1(-1,0) 2(1,0)
0805#2
  rect 0.94x1.37 smd: 1(-0.79,0) 2(0.79,0)
BGA9C40P3X3_126X126X69M
  round 0.21 smd: A1(-0.4,0.4) A2(0,0.4) A3(0.4,0.4) B1(-0.4,0) B2(0,0) B3(0.4,0) C1(-0.4,-0.4) C2(0,-0.4) C3(0.4,-0.4)
BGA30C40P6X5_275X215X69M
  round 0.21 smd: A1(-1,0.8) A2(-0.6,0.8) A3(-0.2,0.8) A4(0.2,0.8) A5(0.6,0.8) A6(1,0.8) B1(-1,0.4) B2(-0.6,0.4) B3(-0.2,0.4) B4(0.2,0.4) B5(0.6,0.4) B6(1,0.4) C1(-1,0) C2(-0.6,0) C3(-0.2,0) C4(0.2,0) C5(0.6,0) C6(1,0) D1(-1,-0.4) D2(-0.6,-0.4) D3(-0.2,-0.4) D4(0.2,-0.4) D5(0.6,-0.4) D6(1,-0.4) E1(-1,-0.8) E2(-0.6,-0.8) E3(-0.2,-0.8) E4(0.2,-0.8) E5(0.6,-0.8) E6(1,-0.8)
BOURNS_3296Y
  rect 1.55x1.55 hole 0.95: 1(2.54,1.27)
  round 1.55 hole 0.95: 2(0,-1.27) 3(-2.54,1.27)
CAPC1005X50L
  rect 0.4x0.5 smd: 1(-0.45,0) 2(0.45,0)
CAPC1608X90L
  rect 0.69x0.83 smd: 1(-0.67,0) 2(0.67,0)
EVK_MAXIMPAD
  oval 5.08x1.905 hole 1: 1(0,0)
FCI_10103592-0001LF
  rect 0.4x1.65 smd: 1(1.3,2.925) 2(0.65,2.925) 3(0,2.925) 4(-0.65,2.925) 5(-1.3,2.925)
  custom 0.669x0.669 hole 0.7x1.3: 6(-4.1,0) 9(4.1,0)
  custom 0.35x0.35 hole 1.05x0.65: 7(-2.425,3.08) 8(2.425,3.08)
  rect 1.375x2.5 smd: 10(0.938,-0.2) 11(-0.938,-0.2)
IND_2016
  rect 0.9x1.6 smd: 1(-0.8,0) 2(0.8,0)
IND_2520
  rect 1.15x2.15 smd: 1(-1.015,0) 2(1.015,0)
JST_S2B-PH-K-X
  rect 1.55x1.55 hole 0.95: 1(0,0)
  round 1.55 hole 0.95: 2(-2,0)
JUMPER_3WAY
  rect 1.65x1.65 hole 1.05: 1(0,0)
  round 1.651 hole 1.05: 2(0,2.54) 3(2.54,0) 4(0,-2.54)
LED_R6GHBHC
  rect 0.7x0.6 smd: 1(-0.75,0.875) 3(-0.75,-0.875) 4(0.75,0.875) 6(0.75,-0.875)
  rect 0.9x0.6 smd: 2(-0.85,0) 5(0.85,0)
LEDC1608X80M
  rect 1.1x1.05 smd: A(0.9,0) K(-0.9,0)
QFN50P500X500X100-33V2M
  oval 1x0.3 smd: 1(-2.5,1.75) 2(-2.5,1.25) 3(-2.5,0.75) 4(-2.5,0.25) 5(-2.5,-0.25) 6(-2.5,-0.75) 7(-2.5,-1.25) 8(-2.5,-1.75) 17(2.5,-1.75) 18(2.5,-1.25) 19(2.5,-0.75) 20(2.5,-0.25) 21(2.5,0.25) 22(2.5,0.75) 23(2.5,1.25) 24(2.5,1.75)
  oval 0.3x1 smd: 9(-1.75,-2.5) 10(-1.25,-2.5) 11(-0.75,-2.5) 12(-0.25,-2.5) 13(0.25,-2.5) 14(0.75,-2.5) 15(1.25,-2.5) 16(1.75,-2.5) 25(1.75,2.5) 26(1.25,2.5) 27(0.75,2.5) 28(0.25,2.5) 29(-0.25,2.5) 30(-0.75,2.5) 31(-1.25,2.5) 32(-1.75,2.5)
  rect 3.25x3.25 smd: 33(0,0)
QFN50P800X800X80-57M
  oval 0.9x0.3 smd: 1(-4,3.25) 2(-4,2.75) 3(-4,2.25) 4(-4,1.75) 5(-4,1.25) 6(-4,0.75) 7(-4,0.25) 8(-4,-0.25) 9(-4,-0.75) 10(-4,-1.25) 11(-4,-1.75) 12(-4,-2.25) 13(-4,-2.75) 14(-4,-3.25) 29(4,-3.25) 30(4,-2.75) 31(4,-2.25) 32(4,-1.75) 33(4,-1.25) 34(4,-0.75) 35(4,-0.25) 36(4,0.25) 37(4,0.75) 38(4,1.25) 39(4,1.75) 40(4,2.25) 41(4,2.75) 42(4,3.25)
  oval 0.3x0.9 smd: 15(-3.25,-4) 16(-2.75,-4) 17(-2.25,-4) 18(-1.75,-4) 19(-1.25,-4) 20(-0.75,-4) 21(-0.25,-4) 22(0.25,-4) 23(0.75,-4) 24(1.25,-4) 25(1.75,-4) 26(2.25,-4) 27(2.75,-4) 28(3.25,-4) 43(3.25,4) 44(2.75,4) 45(2.25,4) 46(1.75,4) 47(1.25,4) 48(0.75,4) 49(0.25,4) 50(-0.25,4) 51(-0.75,4) 52(-1.25,4) 53(-1.75,4) 54(-2.25,4) 55(-2.75,4) 56(-3.25,4)
  rect 6.7x6.7 smd: 57(0,0)
QFN80P400X400X80-13M
  oval 1.1x0.35 smd: 1(-1.9,0.8) 2(-1.9,0) 3(-1.9,-0.8) 7(1.9,-0.8) 8(1.9,0) 9(1.9,0.8)
  oval 0.35x1.1 smd: 4(-0.8,-1.9) 5(0,-1.9) 6(0.8,-1.9) 10(0.8,1.9) 11(0,1.9) 12(-0.8,1.9)
  rect 2.25x2.25 smd: 13(0,0)
RESC1005X50L
  rect 0.4x0.5 smd: 1(-0.45,0) 2(0.45,0)
RESC1608X90L
  rect 0.69x0.83 smd: 1(-0.67,0) 2(0.67,0)
SAMTEC_TSW-102-07-X-S
  rect 1.75x1.75 hole 1.15: 1(0,0)
  round 1.75 hole 1.15: 2(2.54,0)
SAMTEC_TSW-102-26-X-T
  rect 1.5x1.5 hole 0.9: 1(0,0)
  round 1.5 hole 0.9: 2(2.54,0) 3(0,-2.54) 4(2.54,-2.54) 5(0,-5.08) 6(2.54,-5.08)
SAMTEC_TSW-103-07-T-S
  rect 1.75x1.75 hole 1.15: 1(0,0)
  round 1.75 hole 1.15: 2(2.54,0) 3(5.08,0)
SOP63P600X175-16M
  rect 1.75x0.4 smd: 1(-2.8,2.223) 2(-2.8,1.588) 3(-2.8,0.953) 4(-2.8,0.318) 5(-2.8,-0.317) 6(-2.8,-0.952) 7(-2.8,-1.587) 8(-2.8,-2.222) 9(2.8,-2.223) 10(2.8,-1.588) 11(2.8,-0.953) 12(2.8,-0.318) 13(2.8,0.317) 14(2.8,0.952) 15(2.8,1.587) 16(2.8,2.222)
SOP65P490X110-8M
  rect 1.6x0.45 smd: 1(-2.35,0.975) 2(-2.35,0.325) 3(-2.35,-0.325) 4(-2.35,-0.975) 5(2.35,-0.975) 6(2.35,-0.325) 7(2.35,0.325) 8(2.35,0.975)
SOP65P640X120-14M
  rect 1.65x0.45 smd: 1(-3.05,1.95) 2(-3.05,1.3) 3(-3.05,0.65) 4(-3.05,0) 5(-3.05,-0.65) 6(-3.05,-1.3) 7(-3.05,-1.95) 8(3.05,-1.95) 9(3.05,-1.3) 10(3.05,-0.65) 11(3.05,0) 12(3.05,0.65) 13(3.05,1.3) 14(3.05,1.95)
SOT50P160X90-3M
  rect 1.05x0.4 smd: 1(-0.9,0.5) 2(-0.9,-0.5) 3(0.9,0)
SOT65P210X110-5M
  rect 1.1x0.45 smd: 1(-1.2,0.65) 2(-1.2,0) 3(-1.2,-0.65) 4(1.2,-0.65) 5(1.2,0.65)
SOT95P237X112-3M
  oval 1.6x0.65 smd: 1(-1.1,0.95) 2(-1.1,-0.95) 3(1.1,0)
SOT95P280X145-5M
  rect 1.25x0.65 smd: 1(-1.45,0.95) 2(-1.45,0) 3(-1.45,-0.95) 4(1.45,-0.95) 5(1.45,0.95)
SOT95P280X145-6M
  rect 1.25x0.65 smd: 1(-1.45,0.95) 2(-1.45,0) 3(-1.45,-0.95) 4(1.45,-0.95) 5(1.45,0) 6(1.45,0.95)
SULLINS_PXC06SAAN
  rect 1.75x1.75 hole 1.15: 1(0,0)
  round 1.75 hole 1.15: 2(2.54,0) 3(5.08,0) 4(7.62,0) 5(10.16,0) 6(12.7,0)
SULLINS_PXC10SAAN
  rect 1.75x1.75 hole 1.15: 1(0,0)
  round 1.75 hole 1.15: 2(2.54,0) 3(5.08,0) 4(7.62,0) 5(10.16,0) 6(12.7,0) 7(15.24,0) 8(17.78,0) 9(20.32,0) 10(22.86,0)
SW_CL-SB-12B-1X
  round 0.8 hole 0.9 unplated: (0,3.4) (0,-3.4)
  rect 1.4x1.2 smd: 1(-2.2,2.5) 2(2.2,0) 3(-2.2,-2.5)
SW_EVQ-Q2X03W
  rect 3.2x1 smd: 1(-3.4,-2.5) 2(3.4,-2.5) 3(-3.4,2.5) 4(3.4,2.5)
TP_180P120D460H
  round 1.6 hole 1: 1(0,0)
TP_C25H12
  round 0.635 hole 0.305: 1(0,0)
TP_C127H81
  round 1.27 hole 0.813: 1(0,0)
TP_C240H180
  round 2.4 hole 1.8: 1(0,0)
TP_C340H160
  round 3.4 hole 1.6: 1(0,0)
TRAN_IRF_PQFN8_SINGLE_B
  rect 0.77x0.39 smd: 1(-1.54,0.975) 2(-1.54,0.325) 3(-1.54,-0.325) 4(-1.54,-0.975) 6(1.54,-0.325) 7(1.54,0.325) 8(1.54,0.975)
  custom 0.635x0.635 smd: 5(1.54,-0.975)
unnamed#2
  round 5.08 hole 3.175: (0,0)
XTAL320X250X070M
  rect 1.4x1.2 smd: 1(-1.1,-0.8) 2(1.1,-0.8) 3(1.1,0.8) 4(-1.1,0.8)

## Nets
+1.8V: C111.2 J101.2 R160.1 U103.5
+2.5V: C113.2 C151.1 R156.1 U100.40 U104.5
+3.3V: C115.2 C150.1 C157.2 C158.2 C221.2 C222.2 C268.2 C269.2 D100.A D101.A D102.A D103.A J100.2 J101.4 R100.2 R118.2 R158.1 R163.2 R214.2 R283.1 R289.1 R293.2 R294.1 R295.2 R296.1 R297.2 R298.1 R299.2 R300.1 U100.2 U100.22 U102.5 U107.11 U205.7 U205.13(VDDIO) U211.2
VBATT: C7.2 C15.1 J9.1 U1.E3 VBATT.1(TP1)
VSS: C271.2 C272.2 C274.2 C275.2 C276.2 C277.2 U200.4 U201.4 U202.4 U203.4 U211.1(OUT)
AMUX: AMUX.1(TP1) J2.2 R285.1 U1.C1
BST: C4.1 U1.C5
CHGIN: C2.2 CHGIN.1(TP1) J1.1 J10.1 U1.E1
CTSN: U100.39 U101.8
DCDN: U100.25 U101.7
DSRN: U100.24 U101.6
DTRN: U100.28 U101.31
GPIO: GPIO.1(TP1) J2.3 J3.2 U1.B1
GROUND: C1.1 C2.1 C3.1 C5.1 C6.1 C7.1 C8.1 C9.1 C10.2 C11.2 C12.1 C13.2 C14.1 C15.2 C16.1 C17.1 C18.1 C19.1 C20.1 C21.1 C22.1 C23.1 C24.1 C25.1 C26.1 C27.1 C28.1 C29.1 C30.1 C31.1 C32.1 C33.1 C108.1 C110.1 C111.1 C112.1 C113.1 C114.2 C115.1 C118.1 C120.1 C129.1 C134.1 C150.2 C151.2 C152.1 C153.1 C154.1 C155.2 C156.1 C157.1 C158.1 C159.2 C200.1 C202.2 C204.1 C205.1 C207.2 C208.1 C210.1 C212.2 C214.1 C215.1 C217.2 C218.1 C220.1 C221.1 C222.1 C223.1 C224.2 C226.2 C227.2 C228.1 C234.1 C235.1 C236.1 C237.1 C238.1 C239.1 C240.1 C241.1 C242.1 C244.1 C248.1 C249.1 C250.1 C251.1 C252.1 C268.1 C269.1 C271.1 C272.1 C273.1 C274.1 C275.1 C276.1 C277.1 GND1.1(TP1) GND2.1 GND3.1 GND4.1 GND5.1(TP1) GND6.1(TP1) GND7.1(TP1) GND8.1 J1.5 J2.10 J3.3 J4.3 J6.5 J100.6 J208.1 L2.1 L2.2 L3.1 L3.2 L4.1 L4.2 L5.1 L5.2 Q100.2(S) Q101.2(S) Q204.2(S) Q206.2(S) R4.2 R12.3 R13.2 R110.2 R115.2 R122.2 R137.2 R138.2 R157.2 R159.2 R161.2 R206.1 R208.2 R210.1 R211.2 R213.2 R226.1 R230.2 R231.1 R233.2 R234.2 R240.1 R243.2 R244.1 R245.2 R247.2 R252.1 R255.2 R257.1 R258.2 R260.2 R262.2 R268.2 R282.2 R287.2 R301.2 RT1.2 SW1.4 SW2.3 U1.B3 U1.C3 U1.E5 U100.1 U100.3 U100.4 U100.23 U100.35 U101.4 U101.17 U101.20 U101.24 U101.26 U101.33 U102.2 U103.2 U104.2 U107.5 U107.13 U108.2 U108.5(WP) U205.4 U205.8 U205.9 U206.A3 U206.B2 U207.2 U209.15 U210.2 U211.4 Y101.2 Y101.4
IBATT: C228.2 R269.2 U209.7
IBATT_SNS: BATTN.1(TP1) J9.2 J208.2 R261.1 U206.C1
IBATT_SNS_RNG: J100.5 Q204.1 R284.2 U206.A2
IN_SBB: C1.2 C16.2 IN_SBB.1(TP1) R5.2 U1.E4
INLDO: C13.1 C18.2 INLDO.1(TP1) R11.1 U1.B6
ISET_LDO: R250.1 U205.6
ISET_SBB0: R203.1 U205.2
ISET_SBB1: R224.1 U205.3
ISET_SBB2: R237.1 U205.5
LDO: C5.2 C17.2 C23.2 C25.2 C33.2 J101.6 J207.2 LDO.1(TP1) U1.B5
LED0: LED0.1(TP1) R7.2 U1.A6
LED1: LED1.1(TP1) R8.2 U1.A5
LED2: LED2.1(TP1) R6.2 U1.A4
LXA: L1.2 U1.D4
LXB: C4.2 L1.1 U1.D5
MAXQP03: PO3.1(TP1) U100.52
MAXQP05: PO5.1(TP1) U100.54
NEN: J2.5 J5.2 NEN.1(TP1) U1.A2
NIRQ: J2.6 NIRQ.1(TP1) R14.1 R150.2 U1.C2
NIRQ1: PO0.1(TP1) R152.1 U100.49
NRST: J2.7 J8.1 NRST.1(TP1) R10.1 U1.B2
P01: PO1.1(TP1) R284.1 U100.50
P02: PO2.1(TP1) U100.51
P04: PO4.1(TP1) U100.53
P06: PO6.1(TP1) U100.55
P07: PO7.1(TP1) U100.56
PWRHLD: J2.4 J4.2 PWRHLD.1(TP1) R16.2 U1.A1
REF_1: C236.2 C244.2 R265.1 R279.2 U209.1
RIN: U100.27 U101.3
RTSN: U100.26 U101.32
RXD: U100.43 U101.2
SBB0: C9.2 C19.2 C21.2 C27.2 C30.2 J201.2 R11.2 SBB0.1(TP1) U1.C6
SBB1: C8.2 C20.2 C22.2 C28.2 C31.2 J203.2 SBB1.1(TP1) U1.D6
SBB2: C6.2 C24.2 C26.2 C29.2 C32.2 J205.2 SBB2.1(TP1) U1.E6
SCL: C134.2 J2.8 Q101.3 R107.2 R136.2 SCL.1(TP1) U1.B4
SCL1: J100.3 R118.1 R155.2 R162.1 R304.1 R305.1 U107.9
SDA: C129.2 J2.9 Q100.3 R108.2 R135.2 SDA.1(TP1) U1.A3
SDA1: J100.4 R100.1 R148.2 R164.2 R303.1 R306.1 U107.10
THM: J7.1 THM.1(TP1) U1.D2
THMB: R1.1 R12.1 R15.1 TBIAS.1(TP1) U1.D3
TXD: U100.44 U101.30
UNNAMED_1_10103592-0001LF_I53_SHIELD10: J1.6 J1.7 J1.8 J1.9(SHIELD9) J1.10 J1.11 R3.1 R4.1
UNNAMED_1_CL-SB-12B-1X_I99_2: J5.1 SW2.2
UNNAMED_1_EKCAPNP_I55_1: C10.1 R3.2
UNNAMED_1_EKCAPNP_I69_2: C12.2 R17.1 U1.C4
UNNAMED_1_EKRESSMD_I59_1: DS1.1 R7.1
UNNAMED_1_EKRESSMD_I60_1: DS1.2 R8.1
UNNAMED_1_EKRESSMD_I61_1: DS1.3(C_3) R6.1
UNNAMED_1_EKRESSMD_I72_2: DS1.4 DS1.5 DS1.6 R9.2
UNNAMED_1_EVKJUMPER_I94_2: J7.2 R12.2
UNNAMED_1_HEADER2P_I92_2: J8.2 R16.1
UNNAMED_1_HEADER3P_I78_3: J5.3 R2.1 SW1.1
UNNAMED_1_RESSMD_I44_2: J7.3 R1.2 RT1.1
UNNAMED_1_RESSMD_I93_2: J7.4 R13.1 R15.2
UNNAMED_2_CAPNP_I23_1: C227.1 R264.2 R265.2 R268.1 U207.3
UNNAMED_2_CAPNP_I24_1: C225.1 R263.2 R266.1 R267.1 U207.4
UNNAMED_2_CAPNP_I24_2: C225.2 R266.2 R267.2 R269.1 U207.1
UNNAMED_2_EKCAPNP_I56_2: C234.2 R277.2 R280.1 U210.4
UNNAMED_2_EKCAPNP_I61_2: C235.2 R279.1 U210.5(OUT)
UNNAMED_2_EKRESSMD_I63_2: R280.2 U210.3
UNNAMED_2_MAX14689_I1_COM1: R263.1 U206.B1
UNNAMED_2_MAX14689_I1_COM2: R264.1 U206.B3
UNNAMED_2_MAX14689_I1_NC1: Q204.3 R261.2 R262.1 U206.A1 U206.C3
UNNAMED_4_24AA02_I200_SCL: R162.2 U108.1
UNNAMED_4_24AA02_I200_SDA: R164.1 U108.3
UNNAMED_4_24AA02_I200_VCC: C14.2 R163.1 U108.4
UNNAMED_4_10103592-0001LF_I2_1: C155.1 FB100.1 J6.1
UNNAMED_4_10103592-0001LF_I2_2: J6.2 R123.1
UNNAMED_4_10103592-0001LF_I2_3: J6.3 R103.1
UNNAMED_4_10103592-0001LF_I2_SHIELD10: J6.6 J6.7 J6.8 J6.9(SHIELD9) J6.10 J6.11 R122.1 R142.1
UNNAMED_4_CAPNP_I101_2: C153.2 U100.41 Y101.3(P2)
UNNAMED_4_CAPNP_I105_2: C152.2 U100.42 Y101.1
UNNAMED_4_EKCAPNP_I12_1: C156.2 C159.1 U101.1(VCCIO) U101.16
UNNAMED_4_EKCAPNP_I29_1: C114.1 R142.2
UNNAMED_4_EKRESSMD_I15_2: R123.2 U101.15
UNNAMED_4_EKRESSMD_I16_2: R103.2 U101.14
UNNAMED_4_EKRESSMD_I17_1: R111.1 U101.22
UNNAMED_4_EKRESSMD_I17_2: D100.K(B) R111.2
UNNAMED_4_EKRESSMD_I18_1: R109.1 U101.21
UNNAMED_4_EKRESSMD_I18_2: D101.K(B) R109.2
UNNAMED_4_EKRESSMD_I87_1: R150.1 U107.3
UNNAMED_4_EKRESSMD_I109_1: R155.1 U100.36
UNNAMED_4_EKRESSMD_I113_1: R148.1 U100.37
UNNAMED_4_EKRESSMD_I149_1: Q100.1 R138.1 R141.1
UNNAMED_4_EKRESSMD_I150_1: Q101.1 R137.1 R139.1
UNNAMED_4_EKRESSMD_I151_2: QSDA.1(TP1) R141.2
UNNAMED_4_EKRESSMD_I152_2: QSCL.1(TP1) R139.2
UNNAMED_4_EKRESSMD_I153_1: R135.1 U107.1
UNNAMED_4_EKRESSMD_I154_1: R136.1 U107.2
UNNAMED_4_EKRESSMD_I171_2: R143.2 U107.6
UNNAMED_4_EKRESSMD_I174_1: R156.2 R157.1 U104.4
UNNAMED_4_EKRESSMD_I177_1: R158.2 R159.1 U102.4
UNNAMED_4_EKRESSMD_I190_2: R151.2 R152.2 U107.8
UNNAMED_4_LED_I7_B: D102.K(B) R110.1
UNNAMED_4_LED_I189_B: D103.K(B) R151.1
UNNAMED_4_MAX8512_I5_FB: R160.2 R161.1 U103.4
UNNAMED_6_CAPNP_I21_1: C203.1 R202.2 R205.1 U200.7(OUTB)
UNNAMED_6_CAPNP_I227_2: C238.2 R281.2 R282.1 U209.12
UNNAMED_6_CAPNP_I245_2: C249.2 R285.2 U209.5
UNNAMED_6_CAPNP_I271_2: C208.2 R226.2 R229.1 R295.1 U201.5
UNNAMED_6_CAPNP_I277_1: C209.1 R223.2 R228.1 U201.7(OUTB)
UNNAMED_6_CAPNP_I277_2: C209.2 R228.2 R230.1 R296.2 U201.6
UNNAMED_6_CAPNP_I289_2: C248.2 R224.2 U201.3
UNNAMED_6_CAPNP_I307_2: C214.2 R240.2 R242.1 R297.1 U202.5
UNNAMED_6_CAPNP_I311_1: C213.1 R236.2 R239.1 U202.7(OUTB)
UNNAMED_6_CAPNP_I311_2: C213.2 R239.2 R243.1 R298.2 U202.6
UNNAMED_6_CAPNP_I323_2: C250.2 R237.2 U202.3
UNNAMED_6_CAPNP_I341_2: C218.2 R252.2 R254.1 R299.1 U203.5
UNNAMED_6_CAPNP_I345_1: C219.1 R249.2 R253.1 U203.7(OUTB)
UNNAMED_6_CAPNP_I345_2: C219.2 R253.2 R255.1 R300.2 U203.6
UNNAMED_6_CAPNP_I357_2: C251.2 R250.2 U203.3
UNNAMED_6_CAPNP_I359_2: C200.2 R203.2 U200.3
UNNAMED_6_CAPNP_I441_2: C252.2 R301.1 R302.2 U209.6
UNNAMED_6_EKCAPNP_I10_1: C201.1 R202.1 U200.2
UNNAMED_6_EKCAPNP_I10_2: C201.2 R201.1
UNNAMED_6_EKCAPNP_I203_2: C223.2 U205.1
UNNAMED_6_EKCAPNP_I214_2: C237.2 R286.2 U209.16(VDD)
UNNAMED_6_EKCAPNP_I237_2: C239.2 J201.1 Q200.5 Q200.6 Q200.7 Q200.8 R212.1
UNNAMED_6_EKCAPNP_I261_2: C240.2 J203.1 Q201.5 Q201.6 Q201.7 Q201.8 R227.1
UNNAMED_6_EKCAPNP_I287_1: C206.1 R223.1 U201.2
UNNAMED_6_EKCAPNP_I287_2: C206.2 R222.1
UNNAMED_6_EKCAPNP_I298_2: C241.2 J205.1 Q202.5 Q202.6 Q202.7 Q202.8 R246.1
UNNAMED_6_EKCAPNP_I321_1: C211.1 R236.1 U202.2
UNNAMED_6_EKCAPNP_I321_2: C211.2 R235.1
UNNAMED_6_EKCAPNP_I332_2: C242.2 J207.1 Q203.5 Q203.6 Q203.7 Q203.8 R259.1
UNNAMED_6_EKCAPNP_I355_1: C216.1 R249.1 U203.2
UNNAMED_6_EKCAPNP_I355_2: C216.2 R248.1
UNNAMED_6_EKCAPNP_I377_1: C270.1 U211.3
UNNAMED_6_EKCAPNP_I377_2: C270.2 U211.6
UNNAMED_6_EKCAPNP_I423_2: C273.2 R289.2 U211.5
UNNAMED_6_EKRESSMD_I42_1: C204.2 R206.2 R207.1 R293.1 U200.5
UNNAMED_6_EKRESSMD_I42_2: Q200.1 Q200.2 Q200.3(S3) R207.2 R211.1 VIL_SBB0.1(TP1)
UNNAMED_6_EKRESSMD_I43_1: C203.2 R205.2 R208.1 R294.2 U200.6
UNNAMED_6_EKRESSMD_I99_1: R201.2 R204.1 U200.1
UNNAMED_6_EKRESSMD_I99_2: J200.1 R204.2
UNNAMED_6_EKRESSMD_I207_1: R214.1 U205.14
UNNAMED_6_EKRESSMD_I222_2: R283.2 U205.12
UNNAMED_6_EKRESSMD_I273_2: Q201.1 Q201.2 Q201.3(S3) R229.2 R233.1 VIL_SBB1.1(TP1)
UNNAMED_6_EKRESSMD_I278_1: R222.2 R225.1 U201.1
UNNAMED_6_EKRESSMD_I278_2: J202.1 R225.2
UNNAMED_6_EKRESSMD_I306_2: Q202.1 Q202.2 Q202.3(S3) R242.2 R245.1 VIL_SBB2.1(TP1)
UNNAMED_6_EKRESSMD_I313_1: R235.2 R238.1 U202.1
UNNAMED_6_EKRESSMD_I313_2: J204.1 R238.2
UNNAMED_6_EKRESSMD_I340_2: Q203.1 Q203.2 Q203.3(S3) R254.2 R258.1 VIL_LDO.1(TP1)
UNNAMED_6_EKRESSMD_I347_1: R248.2 R251.1 U203.1
UNNAMED_6_EKRESSMD_I347_2: J206.1 R251.2
UNNAMED_6_EKRESSMD_I439_1: AIN1.1(TP1) R302.1
UNNAMED_6_EKRESSMD_I450_2: R305.2 U205.10
UNNAMED_6_EKRESSMD_I451_2: R306.2 U205.11
UNNAMED_6_EKRESSMD_I452_2: R303.2 U209.14
UNNAMED_6_EKRESSMD_I453_2: R304.2 U209.13
UNNAMED_6_HEADER2P_I444_2: J202.2 Q201.4 R231.2
UNNAMED_6_HEADER2P_I446_2: J204.2 Q202.4 R244.2
UNNAMED_6_HEADER2P_I448_2: J206.2 Q203.4 R257.2
UNNAMED_6_RESSMD_I28_2: J200.2 Q200.4 R210.2
UNNAMED_6_RESSMD_I225_1: AIN7.1(TP1) R281.1
UNNAMED_6_RESSMD_I363_2: Q205.1 Q206.3 R288.2
VADC: Q205.2(S) R277.1 R286.1 R288.1
VIO: C120.2 J2.1 J3.1 J4.1 J101.1 J101.3 J101.5 R10.2 R14.2 R17.2 R107.1 R108.1 R143.1 U107.12(VL)
VL: C3.2 U1.D1(VL) VL.1(TP1)
VLDO: C220.2 R259.2 R260.1 U209.11
VSBB0: C205.2 R212.2 R213.1 U209.8
VSBB1: C210.2 R227.2 R234.1 U209.9
VSBB2: C215.2 R246.2 R247.1 U209.10
VSYS: C11.1 R2.2 R5.1 R9.1 SW2.1 U1.E2 VSYS.1(TP1)
VUSB: C108.2 C110.2 C112.2 C118.2 C154.2 C202.1 C207.1 C212.1 C217.1 C224.1 C226.1 FB100.2 J10.2 J100.1 Q205.3 Q206.1 R115.1 R287.1 U101.19 U102.1 U102.3(SHDN*) U103.1 U103.3(SHDN*) U104.1 U104.3(SHDN*) U200.8 U201.8 U202.8 U203.8 U206.C2(VCC) U207.5 U207.6(VCC)

Pads without a net: J1 2 3 4; J6 4; SW1 2 3; U100 5 6 7 8 9 10 11 12 13 14 15 16 17 18 19 20 21 29 30 31 32 33 34 38 45 46 47 48 57; U101 5 9 10 11 12 13 18 23 25 27 28 29; U107 4 7; U209 2 3 4; U210 1

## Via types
v1: diameter 0.457, hole 0.203, INTERNAL3 to BOTTOM, 84 vias
v2: diameter 0.457, hole 0.203, TOP to BOTTOM, 365 vias
v3: diameter 0.203, hole 0.102, TOP to INTERNAL2, 86 vias
v4: diameter 0.406, hole 0.203, INTERNAL2 to INTERNAL3, 18 vias

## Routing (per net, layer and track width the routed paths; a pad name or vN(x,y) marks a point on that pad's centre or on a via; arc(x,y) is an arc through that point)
+1.8V: length 39.2
  TOP w0.254: U103.5 32.73,90.35 C111.2 32.7,90.85 33.05,91.19 35.74,91.19 36.03,90.89 R160.1
  TOP w0.381: v2(37.72,90.92) 36.78,89.99 R160.1
  BOTTOM w0.381: v2(37.72,90.92) 59.04,90.92 60.93,89.03 64.49,89.03 J101.2
+2.5V: length 26.3
  TOP w0.254: v2(37.56,88.7) 38.17,88.7 38.47,89 U104.5 39.31,89.29 38.86,89.74 38.86,90.37 C113.2 38.85,91.19 R156.1 ; v2(19.41,88.9) 20,88.9 C151.1 19.43,88.89 19.2,89.12 U100.40
  BOTTOM w0.254: v2(37.56,88.7) 20.22,88.7 20.02,88.9 v2(19.41,88.9)
+3.3V: length 280.3
  TOP w0.254: U100.2 7.15,89.62 7.12,89.59 v2(6.3,89.59) ; D101.A 14.1,66.97 14.11,66.98 D100.A ; R163.2 v2(52.72,79.54) ; v2(6.3,81.43) v2(11.88,81.43) 12.37,81.43 C150.1 12.56,81.84 13.2,82.49 U100.22 ; 26.79,90.17 C158.2 ; 22.74,86.85 R118.2 ; D103.A v2(31.83,78.78)
  TOP w0.381: v2(46.23,86.51) 46.03,86.51 45.47,87.07 C268.2 45.5,87.79 C269.2 46.12,88.55 46.53,88.96 U211.2 ; v2(25.27,84.92) v2(23.29,84.92) 22.75,85.46 R118.2 ; v2(24.92,90.95) 24.92,90.25 D102.A 26.64,90.01 26.79,90.17 U102.5 ; v2(31.82,65.47) 26.32,65.47 24.81,66.98 D100.A ; R289.1 v2(51.98,91.68) ; U107.11 23.73,82.21 23.96,82.44 23.96,83.11 C115.2 23.75,83.3 C157.2 23.29,83.06 v2(23.29,82.72) ; 29.81,90.88 30.07,91.14 31.29,91.14 v2(31.84,91.68) ; 29.81,90.88 R158.1 ; 29.81,90.88 29.68,91.01 27.22,91.01 26.84,90.63 C158.2 ; R100.2 22.74,86.85
  INTERNAL3 w0.254: v2(6.3,81.43) v2(6.3,89.59) ; v2(52.72,79.54) v2(52.72,83.96) ; v1(65.1,83.99) v1(65.1,82.03)
  INTERNAL3 w0.381: v2(23.29,82.72) v2(23.29,84.92) ; v1(71.36,49.24) v1(71.36,47.92) ; v1(65.94,68.12) 65.94,67.39 65.89,67.34 v1(65.89,51.59) 65.89,42.37 65.63,42.11 v1(65.63,41.17) v1(65.63,32.61) ; v1(70.93,66.79) v1(70.93,64.18) ; v2(25.27,84.92) 25.27,86.31 24.92,86.66 v2(24.92,90.95) ; v2(46.23,86.51) 46.23,86.62 46.19,86.66 ; v2(60.58,68.12) 60.58,73.86 60.26,74.18 v1(60.26,74.85) v1(60.26,83.99) ; v2(46.23,91.68) 46.23,92.08 46.19,92.12 ; v1(71.82,39.54) 71.82,38.83 71.94,38.71 v1(71.94,38.03) ; v1(72.01,31.39) v1(72.01,29.9)
  INTERNAL3 w0.508: v1(46.19,83.99) 46.19,92.12 46.1,92.21 J100.2 ; v2(31.82,65.47) 31.82,66.08 31.83,66.09 v2(31.83,78.78) 31.83,91.07 31.84,91.07 v2(31.84,91.68)
  BOTTOM w0.254: R283.1 64.48,83.98 64.49,83.99 ; C222.2 60.22,74.81 v1(60.26,74.85) U205.7 ; 64.49,83.99 v1(65.1,83.99) ; 64.49,83.99 v1(60.26,83.99) ; R214.2 65.63,83.46 v1(65.1,83.99) ; v1(65.1,83.99) 65.2,84.08 C221.2 ; U205.13 65.1,80.97 v1(65.1,82.03) ; v2(52.72,83.96) 52.73,83.96 52.76,83.99
  BOTTOM w0.381: v1(72.01,31.39) R297.2 71.47,32.06 70.92,32.61 v1(65.63,32.61) ; R298.1 71.46,29.9 v1(72.01,29.9) ; v2(60.58,68.12) v1(65.94,68.12) 69.93,68.12 70.43,67.61 R299.2 v1(70.93,66.79) ; v1(70.93,64.18) 70.45,64.18 R300.1 ; v2(51.98,91.68) 52.09,91.68 52.1,91.68 ; 52.1,91.68 59.32,91.68 61.09,89.92 62.84,89.92 J101.4 ; 52.1,91.68 v2(46.23,91.68) v2(31.84,91.68) ; v1(71.82,39.54) R295.2 71.31,39.85 69.99,41.17 v1(65.63,41.17) ; R294.1 70.91,47.92 v1(71.36,47.92) ; v2(23.29,82.72) 15.97,82.72 15.96,82.71 13.16,82.71 v2(11.88,81.43) ; v1(65.89,51.59) 69.22,51.59 70.92,49.88 R293.2 v1(71.36,49.24) ; v1(71.94,38.03) R296.1
  BOTTOM w0.508: v1(60.26,83.99) v1(46.19,83.99)
